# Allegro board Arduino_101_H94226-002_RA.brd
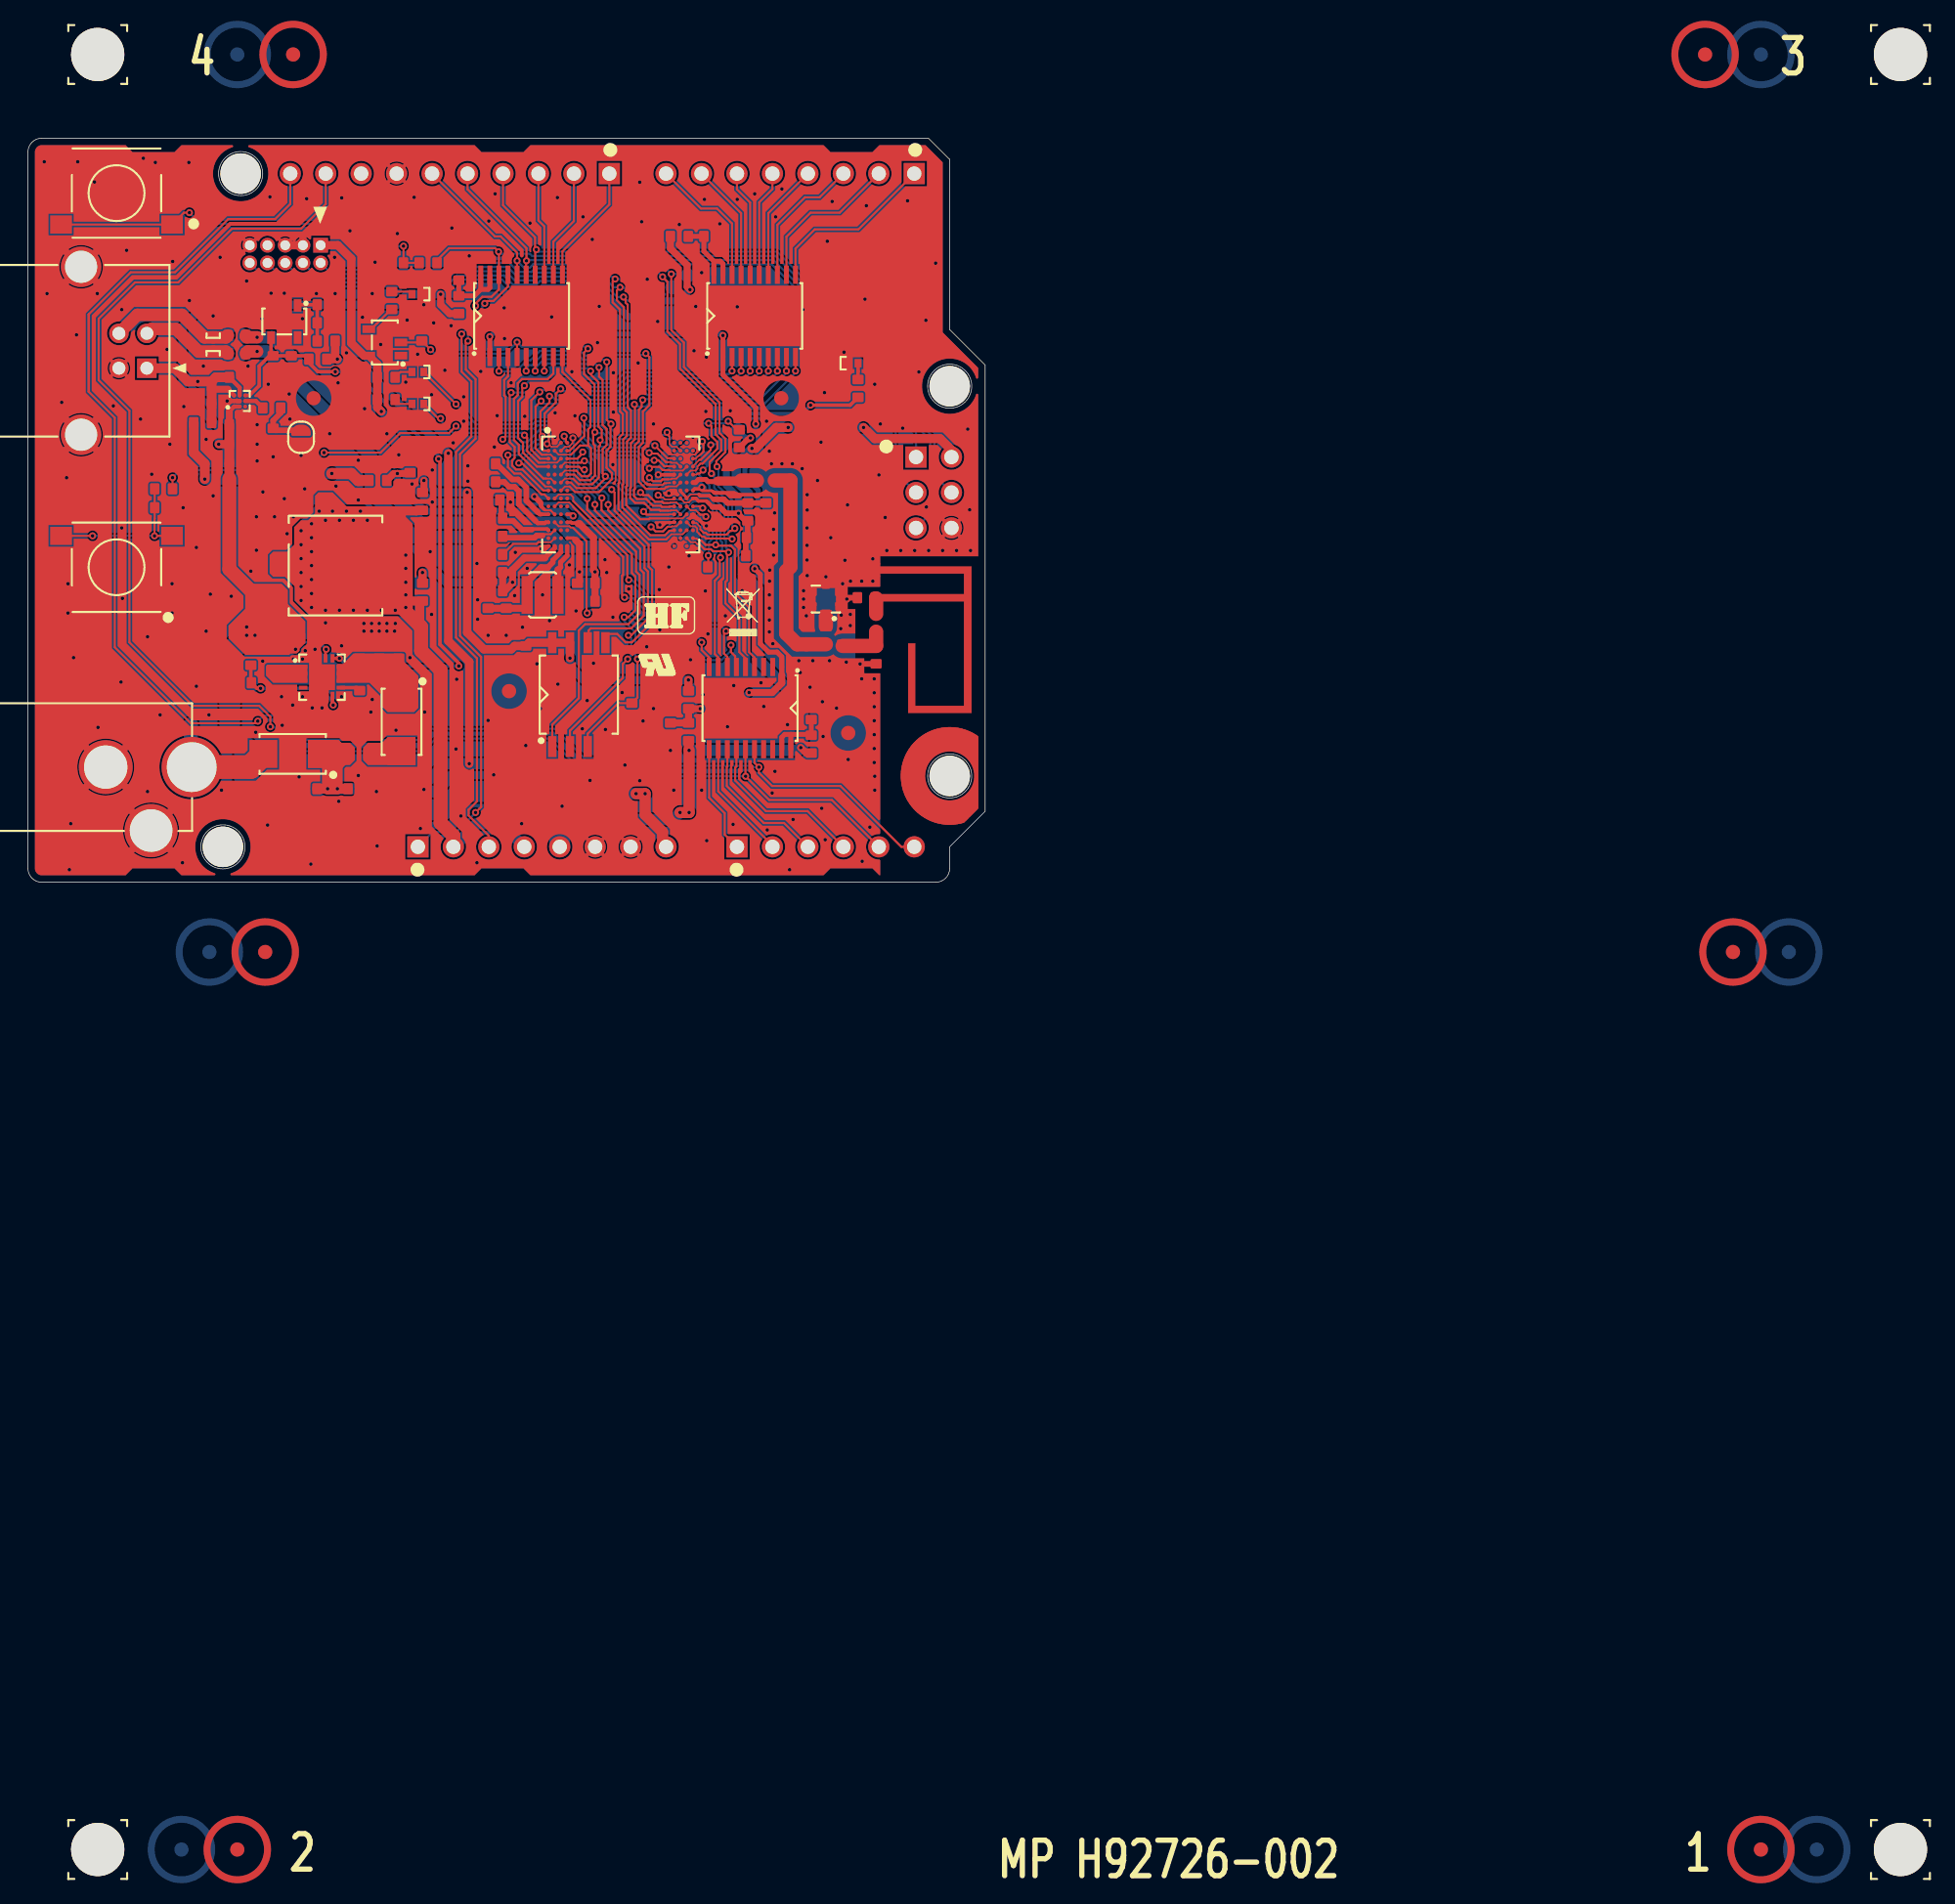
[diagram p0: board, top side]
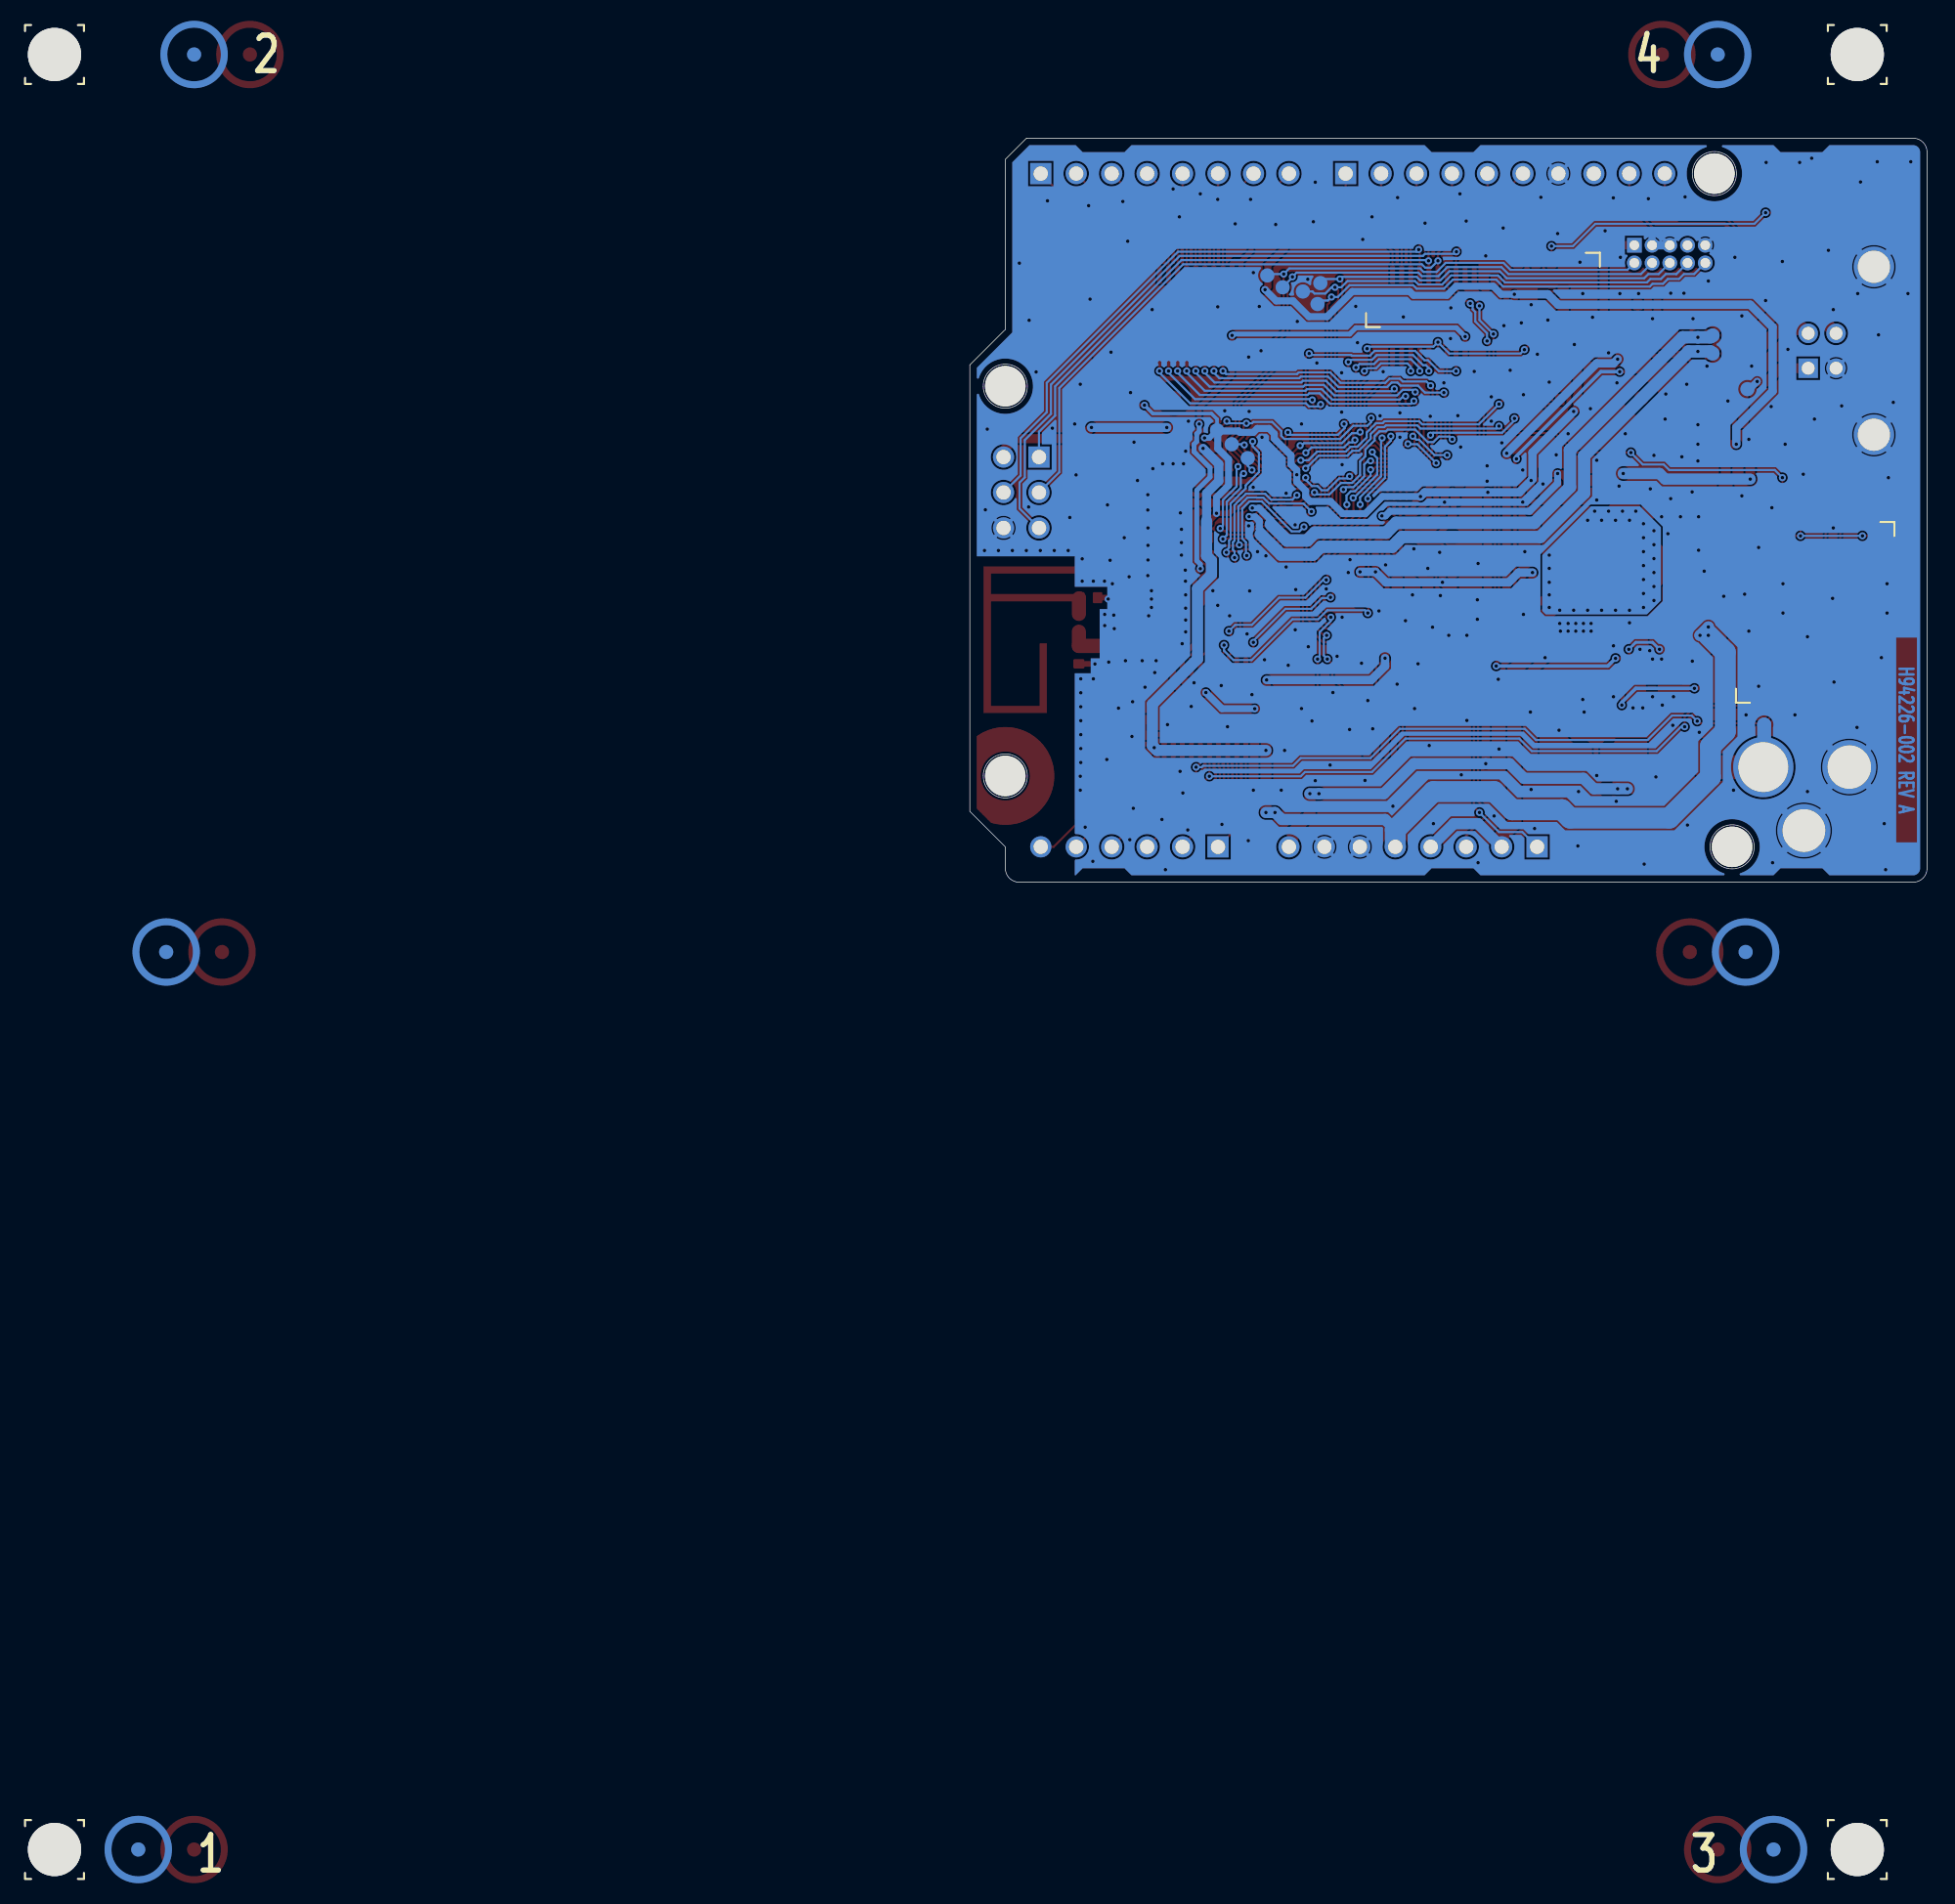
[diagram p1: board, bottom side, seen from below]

Outline 68.58 x 53.34 mm; copper layers: TOP, BOTTOM. Coordinates in mm from the lower left corner of the outline.

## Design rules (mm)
net group USBOTG_DPN: nets USBDN_CONN USBDP_CONN
net group 50OHM_L1>L2: nets BT_ANT_50 BT_AOUT_50 N385362 N385442
net group POWER_TRACE: nets CURIE_VBUS DC_IN_5V_20V N364156 N380754 PV_BATT USB_5P00_PWR V_1P8_ESR3 VDD_PLAT_1P8 VDD_PLAT_3P3 VSYS

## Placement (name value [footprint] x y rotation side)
C11  4.7uF  [0603X90H]  14.17 18 270 top
C12  4.7uF  [0603X90H]  25.17 16.7 180 top
C13  10UF  [0603X90H]  20.47 27.4 270 top
C14  22uF  [0603X90H]  20.17 17.5 90 top
C15  0.033uF  [0603X90H]  23.77 13.1 0 top
C16  4.7uF  [0603X90H]  23.77 16.7 180 top
C17  4.7uF  [0603X90H]  27.37 30 180 top
C18  4.7uF  [0603X90H]  15.07 36.2 90 top
C19  33pF  [0603X90H]  9.72 26.85 90 top
C20  10UF  [0603X90H]  52.87 26.55 0 top
C21  10UF  [0603X90H]  52.12 24.71 90 top
C22  0.1uF  [0603X90H]  52.07 23.41 90 top
C23  10UF  [0603X90H]  33.17 27.4 270 top
C24  0.1uF  [0603X90H]  33.37 26.1 270 top
C25  4.7uF  [0603X90H]  41.27 21.45 90 top
C26  0.1uF  [0603X90H]  41.27 20.15 90 top
C28  0.1uF  [0603X90H]  33.37 24.8 270 top
C29  4.7uF  [0603X90H]  32.97 19 0 top
C30  0.1uF  [0603X90H]  34.27 19 0 top
C31  4.7uF  [0603X90H]  33.37 20.9 270 top
C32  0.1uF  [0603X90H]  33.37 22.2 270 top
C33  4.7uF  [0603X90H]  39.37 20.8 0 top
C35  0.1uF  [0603X90H]  32.87 30 270 top
C36  0.1uF  [0603X90H]  20.07 6.7 270 top
C37  4.7nH  [0603X90H]  60.77 16.3 180 top
C38  NP  [0603X90H]  55.77 17.7 0 top
C39  0.1uF  [0603X90H]  15.07 32.8 90 top
C41  33pF  [0603X90H]  26.27 44.4 270 top
C42  4.7uF  [0603X90H]  12.52 34.3 270 top
C43  0.1uF  [0603X90H]  46.03 10.78 0 top
C44  0.1uF  [0603X90H]  35.67 16.3 0 top
C45  0.1uF  [0603X90H]  33.37 23.5 270 top
C46  NP  [0603X90H]  55.27 28.8 270 top
C47  NP  [0603X90H]  51.07 29.4 0 top
C48  0.1uF  [0603X90H]  32.87 28.7 270 top
C49  10UF  [0603X90H]  15.07 30 90 top
C50  4.7uF  [0603X90H]  23.57 6.7 90 top
C51  0.1uF  [0603X90H]  56.12 12.3 180 top
C52  0.1uF  [0603X90H]  30.87 43.8 180 top
C53  0.1uF  [0603X90H]  49.07 46.3 90 top
C54  0.1uF  [0603X90H]  21.37 41.4 90 top
C55  0.1uF  [0603X90H]  18.87 37.1 0 top
D10  GREEN  [LED_100X60X25H_SMLP13]  59.05 37.21 0 top
D13  GREEN  [LED_100X60X25H_SMLP13]  27.94 42.16 180 top
D14  GREEN  [LED_100X60X25H_SMLP13]  27.94 36.58 180 top
D15  SML-P11UTT86  [LED_100X60X25H_SMLP13]  27.94 34.29 180 top
D17  RSX501L-20TE25  [DIO2_450X260X220H]  18.97 9.2 180 top
D18  RSX501L-20TE25  [DIO2_450X260X220H]  26.77 11.5 270 top
ESD10  CLAMP  [DIO_SOD882]  13.27 37.4 270 top
ESD11  CLAMP  [DIO_SOD882]  13.27 39.7 90 top
J10  8 PIN SOCKET  [CONF1X8-254P_2104X240X850H_TH]  36.83 2.54 0 top
J11  10 PIN SOCKET  [CONF1X10-254P_2612X240X850H_TH]  30.23 50.8 180 top
J12  2X3 PIN HEADER  [CONM2X3-254P_762X500X860H_TH]  64.9 27.94 270 top
J13  8 PIN SOCKET  [CONF1X8-254P_2104X240X850H_TH]  54.61 50.8 180 top
J14  6 PIN SOCKET  [CONF1X6-254P_1596X240X850H_TH]  57.15 2.54 0 top
J15  20021111-00010T4LF  [CONM2X5-127P_1270X559X533H_TH]  18.43 45.03 180 top
J16  2DC-0005D200  [CON_JACK_880X1350X1135H_EJ508A]  5.59 8.26 270 top
J17  AU-Y1007-2-R USB  [CON_USB_1204X1650X1115_AUY1007]  3.81 38.1 90 top
J18  MHF4  [CONN_COAX_MHF4]  57.17 20.3 0 top
L10  2.2uH  [0806X100H]  17.87 16 90 top
L12  22uH  [COIL_300X300X120H_NRH3012]  36.87 20.6 0 top
L13  300Ohm_100M  [0603X90H]  23.72 9.2 90 top
NOREF  -  []  109.35 0 90 top
NOREF#2  -  []  80.16 -64.34 0 top
NOREF#3  -  []  0 1 0 top
NOREF#4  -  []  8.96 31.78 0 top
NOREF#5  -  [unnamed#2]  17 -5 0 top
NOREF#6  -  []  105.16 -64.34 0 top
NOREF#7  -  []  9 -9 0 top
NOREF#8  -  []  61.47 20.31 0 top
NOREF#9  -  []  62.45 9.7 0 top
NOREF#10  -  []  3.61 -74.34 90 top
NOREF#11  -  [unnamed#2]  20.47 34.7 0 top
NOREF#12  -  []  -70.12 -152.57 0 top
NOREF#13  -  []  105.16 54.34 180 top
NOREF#14  -  []  0 -71.34 0 top
NOREF#15  -  []  120.62 59.13 0 top
NOREF#16  -  []  59 -1 0 top
NOREF#17  -  []  1.36 0 90 top
NOREF#18  -  [unnamed#2]  58.77 10.7 0 top
NOREF#19  -  []  59 -9 180 top
NOREF#20  -  []  13.97 -60.8 0 top
NOREF#21  -  []  138.16 -8 90 top
NOREF#22  -  []  134.16 -69.34 0 top
NOREF#23  -  [unnamed#2]  34.47 13.7 0 top
NOREF#24  -  []  19.97 -70.8 0 top
NOREF#25  -  []  5 59.34 90 top
NOREF#26  -  []  130.16 54.34 180 top
NOREF#27  -  []  80.16 -9 0 top
NOREF#28  -  []  68.58 5.08 0 top
NOREF#29  -  []  5 59.34 0 top
NOREF#30  -  []  66.04 39.62 0 top
NOREF#31  -  []  26.91 53.34 90 top
NOREF#32  -  []  0.41 53.14 0 top
NOREF#33  -  []  44.87 20 0 top
NOREF#34  -  []  9 -1 0 top
NOREF#35  -  []  22 -71.34 0 top
NOREF#36  -  []  17 -5 0 top
NOREF#37  -  []  70.58 26.24 0 top
NOREF#38  -  []  59 -64.34 0 top
NOREF#39  -  []  1 0 0 top
NOREF#40  -  []  34 -1 0 top
NOREF#41  -  []  34 -9 180 top
NOREF#42  -  []  138.77 -2.21 0 top
NOREF#43  -  []  19 59.34 0 top
NOREF#44  -  []  68.58 5.08 0 top
NOREF#45  -  []  66.04 2.54 0 top
NOREF#46  -  []  15.24 50.8 0 top
NOREF#47  -  []  64.52 53.34 0 top
NOREF#48  -  []  124.16 -69.34 0 top
NOREF#49  -  []  66.04 0.17 0 top
NOREF#50  -  []  0 -22.73 0 top
NOREF#51  -  []  105.16 -1 0 top
NOREF#52  -  []  122.16 -5 0 top
NOREF#53  -  [unnamed#2]  124.16 -69.34 180 top
NOREF#54  -  []  34 54.34 180 top
NOREF#55  -  []  95.16 58.34 0 top
NOREF#56  -  []  -29.1 -119.83 0 top
NOREF#57  -  [unnamed#2]  15 -69.34 0 top
NOREF#58  -  []  5 -69.34 0 top
NOREF#59  -  []  105.16 -9 180 top
NOREF#60  -  []  13.97 2.54 0 top
NOREF#61  -  []  120.16 59.34 0 top
NOREF#62  -  []  0 61.34 0 top
NOREF#63  -  []  17 -5 0 top
NOREF#64  -  []  135.84 -70.48 0 top
NOREF#65  -  []  9 -9 180 top
NOREF#66  -  []  -10.69 95.32 0 top
NOREF#67  -  []  45.07 15.6 0 top
NOREF#68  -  []  34 -64.34 0 top
NOREF#69  -  [unnamed#2]  19 59.34 0 top
NOREF#70  -  []  104.97 -64.8 0 top
NOREF#71  -  [unnamed#2]  122.16 -5 180 top
NOREF#72  -  []  1 -63.34 0 top
NOREF#73  -  [unnamed#2]  5 59.34 0 top
NOREF#74  -  []  65.04 0 0 top
NOREF#75  -  []  13.97 2.54 0 top
NOREF#76  -  []  130.16 -9 0 top
NOREF#77  -  [unnamed#2]  134.16 59.34 180 top
NOREF#78  -  []  0 61.34 0 top
NOREF#79  -  []  130.16 -9 180 top
NOREF#80  -  []  136.16 -74.34 90 top
NOREF#81  -  [unnamed#2]  120.16 59.34 180 top
NOREF#82  -  []  105.16 -9 0 top
NOREF#83  -  []  51.17 19.8 0 top
NOREF#84  -  [unnamed#2]  53.97 34.7 0 top
NOREF#85  -  []  13.97 -60.8 0 top
NOREF#86  -  []  130.16 -1 0 top
NOREF#87  -  []  9 -9 0 top
NOREF#88  -  []  0 51.84 0 top
NOREF#89  -  []  231.19 -5.6 0 top
NOREF#90  -  []  -63.77 -150.03 0 top
NOREF#91  -  []  54.97 60.2 0 top
NOREF#92  -  []  15 -69.34 0 top
NOREF#93  -  []  123.92 -60.8 0 top
NOREF#94  -  []  66.04 7.62 0 top
NOREF#95  -  []  9 -64.34 0 top
NOREF#96  -  []  66.04 35.56 0 top
NOREF#97  -  []  66.04 51.82 0 top
NOREF#98  -  []  83.97 -69.8 0 top
NOREF#99  -  []  80.16 54.34 180 top
NOREF#100  -  []  138.08 63.65 0 top
NOREF#101  -  []  85.97 58.2 0 top
NOREF#102  -  []  218.79 72.88 0 top
NOREF#103  -  []  9 54.34 180 top
NOREF#104  -  []  174.48 43.2 0 top
NOREF#105  -  [unnamed#3]  0 0 0 top
NOREF#106  -  []  75.16 61.34 0 top
NOREF#107  -  []  80.16 -9 180 top
NOREF#108  -  []  42 -68.34 0 top
NOREF#109  -  []  59 54.34 180 top
NOREF#110  -  []  33.97 54.2 0 top
NOREF#111  -  []  130.16 -64.34 0 top
NOREF#112  -  []  68.58 37.08 0 top
NOREF#113  -  []  5 -69.34 0 top
NOREF#114  -  []  13.97 -60.8 0 top
NOREF#115  -  [unnamed#2]  134.16 -69.34 180 top
NOREF#116  -  []  80.16 -1 0 top
NOREF#117  -  []  15.24 50.8 0 top
NOREF#118  -  []  68.58 28.01 0 top
NOREF#119  -  [unnamed#2]  5 -69.34 0 top
NOREF#120  -  []  13.97 2.54 0 top
NOREF#121  -  [unnamed#2]  11 -69.34 180 bottom
NOREF#122  -  []  98.16 -68.34 180 bottom
NOREF#123  -  [unnamed#2]  13 -5 180 bottom
NOREF#124  -  []  41 58.34 180 bottom
NOREF#125  -  [unnamed#2]  124.16 59.34 0 bottom
NOREF#126  -  [unnamed#2]  128.16 -69.34 0 bottom
NOREF#127  -  [unnamed#2]  15 59.34 180 bottom
NOREF#128  -  [unnamed#2]  126.16 -5 0 bottom
R10  330  [0603X90H]  59.47 35.4 180 top
R12  22  [0603X90H]  12.52 32.95 270 top
R13  100  [0603X90H]  9.72 28.2 90 top
R14  1K  [0603X90H]  26.07 41.7 180 top
R15  330  [0603X90H]  25.67 36.2 90 top
R16  330  [0603X90H]  25.67 34.6 90 top
R18  0R  [0603X90H]  57.17 17.7 180 top
R19  0R  [0603X90H]  57.67 17 90 top
R23  100  [0603X90H]  28.67 44.4 90 top
R24  NP  [0603X90H]  48.07 22.6 90 top
R27  200K  [0603X90H]  56.12 9.9 180 top
R28  200K  [0603X90H]  30.87 41.4 180 top
R29  200K  [0603X90H]  46.67 46.3 90 top
R30  10K  [0603X90H]  50.97 31.8 180 top
R31  22  [0603X90H]  14.97 39.2 90 top
R32  22  [0603X90H]  14.97 37.9 90 top
R33  10K  [0603X90H]  47.33 10.78 180 top
R34  1.8K  [0603X90H]  47.33 13.08 0 top
R35  22  [0603X90H]  51.57 26.55 0 top
R57  10K  [0603X90H]  15.07 31.4 270 top
R58  0R  [0603X90H]  28.27 27.3 0 top
R59  0R  [0603X90H]  25.07 28.8 270 top
R62  10K  [0603X90H]  43.27 12.2 0 top
R63  0R  [0603X90H]  28.27 20.8 0 top
R65  200K  [0603X90H]  28.22 39.45 180 top
R70  10K  [0603X90H]  15.97 16.2 0 top
R71  10K  [0603X90H]  15.37 14.3 270 top
R73  402  [0603X90H]  17.57 31.9 180 top
R74  698  [0603X90H]  17.47 34 270 top
R75  1000  [0603X90H]  17.57 37.1 0 top
R77  10K  [0603X90H]  26.57 16.7 180 top
R81  3K 1%  [0603X90H]  20.77 37.5 270 top
R82  10K 1%  [0603X90H]  21.37 40.1 90 top
R83  1.5K 1%  [0603X90H]  21.37 38.8 270 top
RLC10  1.2pF  [0603X90H]  60.77 18.6 180 top
RLC11  NP  [0603X90H]  60.07 20.4 90 top
RLC12  10pF  [0603X90H]  52.87 28.8 90 top
SH10  Short_pad  [SHORT_140X180]  19.57 31.9 0 top
SW10  PTS645-S-M-43-SMTR92-LFS  [SW4_600X600X430H_SM_PTS645]  6.35 22.58 180 top
SW12  PTS645-S-M-43-SMTR92-LFS  [SW4_600X600X430H_SM_PTS645]  6.35 49.4 180 top
TPB10  T_POINT  [TP40]  48.67 30.4 180 bottom
TPB11  T_POINT  [TP40]  49.82 31.4 180 bottom
TPB12  T_POINT  [TP40]  47.27 43.5 180 bottom
TPB13  T_POINT  [TP40]  46.17 42.65 180 bottom
TPB14  T_POINT  [TP40]  43.47 42.95 180 bottom
TPB15  T_POINT  [TP40]  44.72 42.35 180 bottom
TPB16  T_POINT  [TP40]  43.67 41.45 180 bottom
TPB17  T_POINT  [TP40]  15.37 37.9 180 bottom
TPB18  T_POINT  [TP40]  15.37 39.2 180 bottom
TPB19  T_POINT  [TP40]  12.87 35.35 180 bottom
TPB20  T_POINT  [TP40]  11.67 11.3 180 bottom
TPB21  T_POINT  [TP40]  50.87 32.4 180 bottom
TPB22  T_POINT  [TP40]  45.87 38.1 180 bottom
TPB23  T_POINT  [TP40]  23.37 29.3 180 bottom
U10  TPS62153RGT  [QFN16-50P_300X300X100H_TR]  21.07 14.7 0 top
U11  LSF0108  [SOIC20-65P_440X650X120H]  52.07 40.6 90 top
U12  CURIE_V3  [BGA111_14X24-57P_805X1100X150H]  42.47 27.8 90 top
U13  FPF2496  [BGA9_3X3-40P_121X121X63H]  15.17 34.5 90 top
U14  LSF0108  [SOIC20-65P_440X650X120H]  35.37 40.6 90 top
U15  LSF0108  [SOIC20-65P_440X650X120H]  51.73 12.48 270 top
U16  SN74AUP1G34DBVR  [SOT23-5_160X290X145H]  25.57 38.7 180 top
U17  LM1117DTX-3.3 NOPB  [DPAK-3P_658X610X238H]  21.77 22.7 270 top
U201  W25Q16DVSSIG  [SOIC8-127P_528X528X216H]  39.47 13.45 90 top
U202  R3119N050A  [SOT23-5_160X290X120H]  18.37 40.2 270 top

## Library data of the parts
C11 C12 C15-C18 C22 C24-C26 C28-C33 C35 C42-C45 C48 C50-C53 = CAP NP
C13 C20 C23 C49 = CAP-NP_0: tolerance: 20%
C14 C19 C36 C39 C41 C54 C55 = CAP-NP_0
C21 = CAP NP: tolerance: 20%
C37 C38 C46 C47 = CAP NP_0
D10 D13-D15 = LED_6
D17 D18 = BAS40SL_1
ESD10 ESD11 = AOZ8131DI-05L_100312_000
J10 = 8 PIN SOCKET
J11 = 10 PIN SOCKET_2
J12 = jumper_0
J13 = 8 PIN SOCKET_0
J14 = 8 PIN SOCKET_3
J15 = SHF-105-01-L-D-TH_0
J16 = EJ508A_0
J17 = USB TYPE B_2
J18 = COAX-CONN_2
L10 L13 = INDCT,PWR,63X79,1.9A,2.2uH
L12 = INDCT,PWR,22uH
R10 R12-R16 R23 R27-R29 R31 R32 R35 R65 = RESISTOR
R18 R19 R58 R63 = RESD,0402,5%,1/16W,0: tolerance: 5%
R24 = R_5
R30 R33 R34 R57 R62 R70 R71 R77 R81-R83 = R_5: tolerance: <TOL>
R59 = RESISTOR: tolerance: 5%
R73-R75 = R_5: tolerance: 1%
RLC10-RLC12 = RLC
SH10 = Shorting_pad_2
SW10 SW12 = TCFC2QR1_1
TPB10-TPB23 = T_POINT_S_3
U10 = TPS62143RGT_5
U11 U14 U15 = LSF0108
U12 = CURIE_23
U13 = FPF2496
U16 = SN74AUP1G07DBVR
U17 = NCP1117DT33T5G_0
U201 = M25P16_1
U202 = R3120NxxxA_0

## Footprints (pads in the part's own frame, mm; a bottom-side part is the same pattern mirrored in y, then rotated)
0603X90H
  custom 0.17x0.17 smd: 1(0,0.64) 2(0,-0.64)
0806X100H
  custom 0.2x0.2 smd: 1(-0.8,0) 2(0.8,0)
BGA9_3X3-40P_121X121X63H
  round 0.28 smd: A1(-0.4,0.4) A2(0,0.4) A3(0.4,0.4) B1(-0.4,0) B2(0,0) B3(0.4,0) C1(-0.4,-0.4) C2(0,-0.4) C3(0.4,-0.4)
BGA111_14X24-57P_805X1100X150H
  round 0.28 smd: A2(3.705,4.73) A3(3.705,4.28) A4(3.705,3.83) A21(3.705,-3.83) A22(3.705,-4.28) A23(3.705,-4.73) A24(3.705,-5.18) B1(3.135,5.18) B2(3.135,4.73) B3(3.135,4.28) B4(3.135,3.83) B21(3.135,-3.83) B22(3.135,-4.28) B23(3.135,-4.73) B24(3.135,-5.18) C1(2.565,5.18) C2(2.565,4.73) C3(2.565,4.28) C4(2.565,3.83) C21(2.565,-3.83) C22(2.565,-4.28) C23(2.565,-4.73) C24(2.565,-5.18) D1(1.995,5.18) D2(1.995,4.73) D3(1.995,4.28) D4(1.995,3.83) D21(1.995,-3.83) D22(1.995,-4.28) D23(1.995,-4.73) D24(1.995,-5.18) E1(1.425,5.18) E2(1.425,4.73) E3(1.425,4.28) E4(1.425,3.83) E21(1.425,-3.83) E22(1.425,-4.28) E23(1.425,-4.73) E24(1.425,-5.18) F1(0.855,5.18) F2(0.855,4.73) F3(0.855,4.28) F4(0.855,3.83) F21(0.855,-3.83) F22(0.855,-4.28) F23(0.855,-4.73) F24(0.855,-5.18) G1(0.285,5.18) G2(0.285,4.73) G3(0.285,4.28) G4(0.285,3.83) G21(0.285,-3.83) G22(0.285,-4.28) G23(0.285,-4.73) G24(0.285,-5.18) H1(-0.285,5.18) H2(-0.285,4.73) H3(-0.285,4.28) H4(-0.285,3.83) H21(-0.285,-3.83) H22(-0.285,-4.28) H23(-0.285,-4.73) H24(-0.285,-5.18) J2(-0.855,4.73) J3(-0.855,4.28) J4(-0.855,3.83) J21(-0.855,-3.83) J22(-0.855,-4.28) J23(-0.855,-4.73) J24(-0.855,-5.18) K2(-1.425,4.73) K3(-1.425,4.28) K4(-1.425,3.83) K21(-1.425,-3.83) K22(-1.425,-4.28) K23(-1.425,-4.73) K24(-1.425,-5.18) L1(-1.995,5.18) L2(-1.995,4.73) L3(-1.995,4.28) L4(-1.995,3.83) L21(-1.995,-3.83) L22(-1.995,-4.28) L23(-1.995,-4.73) L24(-1.995,-5.18) M2(-2.565,4.73) M3(-2.565,4.28) M4(-2.565,3.83) M21(-2.565,-3.83) M22(-2.565,-4.28) M23(-2.565,-4.73) M24(-2.565,-5.18) N2(-3.135,4.73) N3(-3.135,4.28) N4(-3.135,3.83) N21(-3.135,-3.83) N22(-3.135,-4.28) N23(-3.135,-4.73) N24(-3.135,-5.18) P1(-3.705,5.18) P2(-3.705,4.73) P3(-3.705,4.28) P4(-3.705,3.83) P21(-3.705,-3.83) P22(-3.705,-4.28) P23(-3.705,-4.73) P24(-3.705,-5.18)
  round 0.27 smd: J1(-0.855,5.18) K1(-1.425,5.18) M1(-2.565,5.18) N1(-3.135,5.18)
COIL_300X300X120H_NRH3012
  rect 0.8x2.7 smd: 1(-1.1,0) 2(1.1,0)
CON_JACK_880X1350X1135H_EJ508A
  round 4.32 hole 3.56: 1(0,6.15)
  round 3.81 hole 3.05: 2(4.55,3.24)
  round 3.86 hole 3.1: 3(0,-0.01)
CON_USB_1204X1650X1115_AUY1007
  rect 1.4x1.4 hole 0.92: 1(-1.25,-4.71)
  round 1.4 hole 0.92: 2(1.25,-4.71) 3(1.25,-2.71) 4(-1.25,-2.71)
  round 2.9 hole 2.3: 5(-6.02,0) 6(6.02,0)
CONF1X6-254P_1596X240X850H_TH
  rect 1.52x1.52 hole 1.02: 1(-6.35,0)
  round 1.52 hole 1.02: 2(-3.81,0) 3(-1.27,0) 4(1.27,0) 5(3.81,0) 6(6.35,0)
CONF1X8-254P_2104X240X850H_TH
  rect 1.52x1.52 hole 1.02: 1(-8.89,0)
  round 1.52 hole 1.02: 2(-6.35,0) 3(-3.81,0) 4(-1.27,0) 5(1.27,0) 6(3.81,0) 7(6.35,0) 8(8.89,0)
CONF1X10-254P_2612X240X850H_TH
  rect 1.52x1.52 hole 1.02: 1(-11.43,0)
  round 1.52 hole 1.02: 2(-8.89,0) 3(-6.35,0) 4(-3.81,0) 5(-1.27,0) 6(1.27,0) 7(3.81,0) 8(6.35,0) 9(8.89,0) 10(11.43,0)
CONM2X3-254P_762X500X860H_TH
  rect 1.52x1.52 hole 1.02: 1(-2.54,-1.27)
  round 1.52 hole 1.02: 2(-2.54,1.27) 3(0,-1.27) 4(0,1.27) 5(2.54,-1.27) 6(2.54,1.27)
CONM2X5-127P_1270X559X533H_TH
  rect 1.06x1.06 hole 0.7: 1(-2.54,-0.635)
  round 1.06 hole 0.7: 2(-2.54,0.635) 3(-1.27,-0.635) 4(-1.27,0.635) 5(0,-0.635) 6(0,0.635) 7(1.27,-0.635) 8(1.27,0.635) 9(2.54,-0.635) 10(2.54,0.635)
CONN_COAX_MHF4
  rect 0.6x0.5 smd: 1(0,-1)
  custom 0.145x0.145 smd: 2(-0.96,0) 4(0.96,0)
  rect 0.5x0.5 smd: 3(0,1)
DIO2_450X260X220H
  rect 2x2 smd: A(2.1,0) K(-2.1,0)
DIO_SOD882
  rect 0.3x0.55 smd: 1(-0.35,0) 2(0.35,0)
DPAK-3P_658X610X238H
  rect 1.6x2.5 smd: 1(-2.285,-4.83) 3(2.285,-4.83)
  rect 5.8x6 smd: 2(0,2)
LED_100X60X25H_SMLP13
  rect 0.5x0.6 smd: A(0.425,0) K(-0.425,0)
QFN16-50P_300X300X100H_TR
  rect 0.6x0.27 smd: 1(-1.35,0.75) 2(-1.35,0.25) 3(-1.35,-0.25) 4(-1.35,-0.75) 9(1.35,-0.75) 10(1.35,-0.25) 11(1.35,0.25) 12(1.35,0.75)
  rect 0.27x0.6 smd: 5(-0.75,-1.35) 6(-0.25,-1.35) 7(0.25,-1.35) 8(0.75,-1.35) 13(0.75,1.35) 14(0.25,1.35) 15(-0.25,1.35) 16(-0.75,1.35)
  rect 1.7x1.7 smd: 17(0,0)
SHORT_140X180
  custom 0.2x0.2 smd: 1(0,0.5) 2(0,-0.5)
SOIC8-127P_528X528X216H
  rect 1.5x0.6 smd: 1(-3.725,1.905) 2(-3.725,0.635) 3(-3.725,-0.635) 4(-3.725,-1.905) 5(3.725,-1.905) 6(3.725,-0.635) 7(3.725,0.635) 8(3.725,1.905)
SOIC20-65P_440X650X120H
  rect 1.3x0.35 smd: 1(-2.95,2.925) 2(-2.95,2.275) 3(-2.95,1.625) 4(-2.95,0.975) 5(-2.95,0.325) 6(-2.95,-0.325) 7(-2.95,-0.975) 8(-2.95,-1.625) 9(-2.95,-2.275) 10(-2.95,-2.925) 11(2.95,-2.925) 12(2.95,-2.275) 13(2.95,-1.625) 14(2.95,-0.975) 15(2.95,-0.325) 16(2.95,0.325) 17(2.95,0.975) 18(2.95,1.625) 19(2.95,2.275) 20(2.95,2.925)
SOT23-5_160X290X120H
  rect 0.9x0.55 smd: 1(-1.15,0.95) 2(-1.15,0) 3(-1.15,-0.95) 4(1.15,-0.95) 5(1.15,0.95)
SOT23-5_160X290X145H
  rect 0.9x0.55 smd: 1(-1.15,0.95) 2(-1.15,0) 3(-1.15,-0.95) 4(1.15,-0.95) 5(1.15,0.95)
SW4_600X600X430H_SM_PTS645
  rect 1.55x1.3 smd: 1(-3.975,2.25) 2(3.975,2.25) 3(-3.975,-2.25) 4(3.975,-2.25)
TP40
  round 1.016 smd: 1(0,0)
unnamed#2
  round 1.016 smd: (0,0)
unnamed#3
  round 2.9 hole 3.2 unplated: (13.97,2.54) (15.24,50.8) (66.04,35.56) (66.04,7.62)

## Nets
GND: C11.2 C12.2 C13.2 C14.2 C15.2 C16.2 C17.2 C18.2 C19.2 C20.2 C21.2 C22.2 C23.2 C24.2 C25.2 C26.2 C28.2 C29.2 C30.2 C31.2 C32.2 C33.2 C35.2 C36.2 C37.1 C38.1 C39.2 C41.2 C42.2 C43.2 C44.2 C45.2 C46.1 C47.1 C48.2 C49.2 C50.2 C51.2 C52.2 C53.2 C54.2 C55.2 D10.K D13.K ESD10.2 ESD11.2 J10.6(GND1) J10.7(GND2) J11.7(GND) J12.6(GND) J15.3(GND1) J15.5(GND2) J15.9(GND3) J16.2(GND1) J16.3(GND2) J17.4(GND) J17.5(S1) J17.6(S2) J18.2(GND1) J18.3(GND2) J18.4(GND3) R24.1 R57.1 R62.2 R65.2 R71.2 R73.1 R75.2 R77.2 R82.2 RLC11.1 SH10.2(P2) SW10.1 SW10.2 SW12.3 SW12.4 TPB22.1(TP) TPB23.1(TP) U10.5(FB) U10.6(AGND) U10.7(FSW) U10.15(PGND1) U10.16(PGND2) U10.17(THERM) U11.1(GND) U12.A2(GND2) U12.A24(GND7) U12.C23(GND4) U12.G21(GND6) U12.G24(GND5) U12.K24(VIN_1) U12.L21(AGND) U12.N21(VIN_2) U12.P1(GND1) U12.P22(GND3) U12.P24(GND8) U13.A2(GND1) U13.B2(GND2) U14.1(GND) U15.1(GND) U16.3(GND) U17.1(GND) U201.4(VSS) U202.2(GND1) U202.3(GND2)
VDD_PLAT_1P8: C28.1 U12.M2(VDD_PLAT_1P8)
VDD_PLAT_3P3: C21.1 C22.1 C44.1 J15.1(VCC) R10.1 R15.1 R16.1 R30.1 R34.1 R35.2 R58.1 TPB21.1(TP) U12.E21(AON_IO_VCC) U12.H22(CMP_3P3_VCC) U12.H24(VDD_BLE_SEN) U12.K2(BUCK_VSEL) U16.5(VCC) U201.7(H\O\L\D\) U201.8(VCC)
AD0: J14.1(AD0) U15.11(B8)
AD1: J14.2(AD1) U15.12(B7)
AD2: J14.3(AD2) U15.13(B6)
AD3: J14.4(AD3) U15.14(B5)
AD4_SDA: J11.9(AD4/SDA) J14.5(AD4/SDA) U15.15(B4)
AD5_SCL: J11.10(AD5/SCL) J14.6(AD5/SCL) U15.16(B3)
AD09/SS1_3V_AD5: U12.K21(UART1_RTS/AN09) U12.N24(I2C0_SS_SCL) U15.5(A3)
AD10/SS2_3V_AD0: U12.J2(GPIO/AIN_10) U15.10(A8)
AD11/SS3_3V_AD1: U12.H21(GPIO/AIN_11) U15.9(A7)
AD12/SS4_3V_AD2: U12.H2(GPIO/AIN_12) U15.8(A6)
AD13/SS5_3V_AD3: U12.L2(GPIO/AIN_13) U15.7(A5)
AD14/SS6_3V_AD4: U12.C24(GPIO/AIN_14) U12.N23(I2C0_SS_SDA) U15.6(A4)
AREF: J11.8(AREF)
ATPCTS/IO9_3V_IO14: U12.J22(UART1_CTS) U14.4(A2)
ATPMISO/IO1_3V_IO12: U12.B22(SPI1_M_MISO) U12.G3(ATP_SPI_S_MISO) U14.6(A4)
ATPMOSI/IO3_3V_IO11: U12.E22(SPI1_M_MOSI) U12.F4(ATP_SPI_S_MOSI) U14.7(A5)
ATPSCK/IO2_3V_IO13: R65.1 U12.C21(SPI1_M_SCK) U12.E4(ATP_SPI_S_SCK) U14.5(A3) U16.2(A)
ATPSS/IO0_3V_IO10: U12.D22(SPI1_M_CS0) U12.F3(ATP_SPI_S_CS) U14.8(A6)
BT_ANT_50: C38.2 C46.2 R18.1 R19.1 RLC12.2
BT_AOUT_50: C47.2 RLC12.1 U12.F24(BLE_RF)
CURIE_VBUS: R12.2 R59.2
DBG_AP_JTAG_TCK: J15.4(TCLK) TPB13.1(TP) U12.L23(ATP_TCK)
DBG_AP_JTAG_TDI: J15.8(TDI) TPB15.1(TP) U12.M21(ATP_TDI)
DBG_AP_JTAG_TDO: J15.6(TDO) TPB14.1(TP) U12.M23(ATP_TDO)
DBG_AP_JTAG_TMS: J15.2(TMS) TPB12.1(TP) U12.L24(ATP_TMS)
DBG_AP_JTAG_TRST_N: J15.10(RESET) TPB16.1(TP) U12.K23(ATP_TRST_B)
DC_IN_5V_20V: C36.1 C50.1 D17.K J10.8(VIN) L13.1 R81.1 R83.1
DC_IN_5V_20V_FIL: D18.A L13.2
DC_IN_JACK: D17.A J16.1(DC+) TPB20.1(TP)
I2S_TSCK/IO18_3V_IO2: U11.8(A6) U12.C2(I2S_TSCK)
I2S_TWS/IO19_3V_IO4: U11.6(A4) U12.C1(I2S_TWS)
I2S_TXD/IO20_3V_IO7: U11.3(A1) U12.D1(I2S_TXD)
IO0/RXD: J13.1(IO0/RXD) U11.11(B8)
IO1/TXD: J13.2(IO1/TXD) U11.12(B7)
IO2: J13.3(IO2) U11.13(B6)
IO3/PWM0: J13.4(IO3/PWM) U11.14(B5)
IO4: J13.5(IO4) U11.15(B4)
IO5/PWM1: J13.6(IO5/PWM) U11.16(B3)
IO6/PWM2: J13.7(IO6/PWM) U11.17(B2)
IO7: J13.8(IO7) U11.18(B1)
IO8: J11.1(IO8) U14.11(B8)
IO9/PWM3: J11.2(IO9/PWM) U14.12(B7)
IO10/SS: J11.3(SS/PWM) U14.13(B6)
IO11/MOSI: J11.4(MOSI/PWM) J12.4(MOSI) U14.14(B5)
IO12/MISO: J11.5(MISO) J12.1(MISO) U14.15(B4)
IO13/SCK: J11.6(SCK) J12.3(SCK) U14.16(B3)
IO14_NEW: J10.1(N/A) U14.17(B2)
M_RESET: R13.2 U12.D23(MRESET_B)
MISO1/IO9_3V_IO8: U12.B2(I2S_RSCK) U12.E3(PLT_CLK_0) U14.10(A8)
NOR_SWD_SCL: TPB11.1(TP) U12.D24(BLE_SW_CLK)
NOR_SWD_SDA: TPB10.1(TP) U12.E24(BLE_SWDIO)
PV_BATT: C23.1 C24.1 U12.M1(PV_BATT)
PWM0/SS10_3V_IO3: U11.7(A5) U12.B1(I2S_RWS) U12.H1(PWM0_OUT)
PWM1/SS11_3V_IO5: U11.5(A3) U12.A3(I2S_RXD) U12.G2(PWM1_OUT)
PWM2/SS12_3V_IO6: U11.4(A2) U12.G1(PWM2_OUT)
PWM3/SS13_3V_IO9: U12.F2(PWM3_OUT) U14.9(A7)
RST_SKETCH: J10.3(RESET) J12.5(R\E\S\E\T\) R23.2 U14.18(B1)
RST_SKETCH_3V: U12.F22(ATP_INT0) U14.3(A1)
RXD1/SS9_3V_IO0: U11.10(A8) U12.K22(UART1_RX)
RXLED: D15.K U12.C3(SPI0_M_CS2)
SP0_CLK_MEM: U12.C4(SPI0_M_SCK) U201.6(SCK)
SP0_CS0_MEM: U12.B3(SPI0_M_CS0) U201.1(C\S\)
SP0_MISO_MEM: U12.D4(SPI0_M_MISO) U201.2(MISO)
SP0_MOSI_MEM: U12.D3(SPI0_M_MOSI) U201.5(MOSI)
SP0_WP_MEM~: R62.1 U12.A4(SPI0_M_CS1) U201.3(W\P\)
TRIG_TRUE_D: C55.1 R75.1 R81.2 U10.13(ENA) U13.C3(ONB) U202.4(DOUT)
TXD1/SS8_3V_IO1: U11.9(A7) U12.J21(UART1_TX)
TXLED: D14.K U12.D21(SPI1_M_CS1)
USB_5P00_PWR: C18.1 C42.1 J17.1(VBUS) R12.1 TPB19.1(TP) U13.A3(VIN1) U13.B3(VIN2)
USBDN_CONN: R32.2 TPB17.1(TP) U12.J23(USB_DM)
USBDP_CONN: R31.2 TPB18.1(TP) U12.J24(USB_DP)
V_1P8_ESR3: C29.1 C30.1 L12.1 U12.P3(VDD_HOST_1P8)
V_3P3SRC_VDD1: C13.1 J10.2(IOREF) J10.4(3V3) R58.2 R63.2 U17.2(OUT)
V_3P5_VREFA: C43.1 R33.2 R34.2 U11.2(VREF_A) U14.2(VREF_A) U15.2(VREF_A)
V_5P00SRC_VDD1: C11.1 C14.1 C39.1 C49.1 J10.5(5V0) J12.2(5V0) L10.2 R27.1 R28.1 R29.1 R33.1 R57.2 R70.1 U10.14(VOS) U13.A1(VOUT1) U13.B1(VOUT2) U17.3(IN)
VSYS: C25.1 C26.1 C31.1 C32.1 C33.1 R63.1 U12.L4(VSYS) U12.N4(ESR2_VBATT) U12.P2(ESR1_VBATT)
N137369: ESD11.1 J17.3(DAT+) R31.1
N350266: R30.2 U12.B4(ATP_RST_B) U12.E23(POR_B)
N352539: R24.2 U12.L22(BATT_ISET)
N364156: L12.2 U12.P4(ESR3_LX)
N380754: C35.1 U12.K1(BUCK_VOUT)
N385362: J18.1(ANT-IN) R18.2
N385382: RLC10.2 RLC11.2
N385442: C37.2 R19.2 RLC10.1
N441562: ESD10.1 J17.2(DAT-) R32.1
N463771: C45.1 U12.N2(VDD_PLAT_3P3)
N498391: C20.1 R35.1 U12.G22(COMP_AREF) U12.H23(ADC_3P3_VCC)
N521217: C17.1 R59.1 U12.K4(VDD_USB)
N544606: C12.1 C16.1 D18.K R77.1 U10.10(AVIN) U10.11(PVIN1) U10.12(PVIN2)
N545273: L10.1 U10.1(SW1) U10.2(SW2) U10.3(SW3)
N616057: C48.1 U12.L1(LDO1P8_VOUT)
N656910: C51.1 R27.2 U15.19(VREF_B) U15.20(EN)
N656990: C53.1 R29.2 U11.19(VREF_B) U11.20(EN)
N657094: C52.1 R28.2 U14.19(VREF_B) U14.20(EN)
N692018: R73.2 R74.1 SH10.1(P1)
N692192: R74.2 U13.C2(ISET)
N704436: C15.1 U10.9(SS/TR)
N704444: R70.2 R71.1 U10.8(DEF)
N724575: C41.1 R23.1 SW12.1 SW12.2
N724587: C19.1 R13.1 SW10.3 SW10.4
N726409: D10.A R10.2
N726427: D14.A R15.2
N726455: D15.A R16.2
N765836: C54.1 R82.1 R83.2 U202.1(VDD)
N7255913: R14.1 U16.4(Y)
N7256071: D13.A R14.2

Pads without a net: J15 7; U10 4; U12 A21 A22 A23 B21 B23 B24 C22 D2 E1 E2 F1 F21 F23 G4 G23 H3 H4 J1 J3 J4 K3 L3 M3 M4 M22 M24 N1 N3 N22 P21 P23; U13 C1; U15 3 4 17 18; U16 1; U202 5

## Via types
v1: diameter 0.508, hole 0.254, TOP to BOTTOM, 564 vias

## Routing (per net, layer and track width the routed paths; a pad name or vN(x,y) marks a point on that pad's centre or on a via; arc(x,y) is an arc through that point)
GND: length 209.8
  TOP w0.116: 48.06,30.93 47.78,30.65 47.48,30.65 U12.C23
  TOP w0.15: 48.06,30.93 48.06,31.11 47.66,31.51
  TOP w0.2: U12.L21 46.02,25.81 46,25.78 45.44,25.78 v1(45.28,25.62)
  TOP w0.22: U12.K24 47.67,26.38 48.05,26 48.07,26 48.49,25.58 48.56,25.58 48.59,25.55 v1(48.61,25.55)
  TOP w0.25: 20.82,14.45 U10.17 ; 20.82,14.45 20.32,13.95 U10.5 20.32,12.55 v1(20.37,12.5) ; 20.82,14.45 U10.6 20.82,12.75 v1(21.07,12.5) 21.32,12.75 U10.7 21.32,14.45 U10.17 ; U10.17 20.82,14.95 ; J15.9 16.41,46.18 ; J15.9 15.38,45.15 ; J15.9 15.38,46.18 ; U10.16 20.32,15.45 20.82,14.95 ; J17.4 7.15,37.48 ; J17.4 5.89,37.48 ; J17.4 7.15,36.22 ; J17.4 5.89,36.22 ; v1(47.97,23.7) 47.97,23.78 U12.P24 ; v1(37.77,31.9) 37.74,31.87 U12.A2 ; 42.5,1.86 J10.7 ; J10.7 43.86,3.22 ; J10.7 43.86,1.86 ; J10.7 42.5,3.22 ; 20.82,14.95 U10.15 ; 25.74,51.48 J11.7 ; J11.7 27.09,51.48 ; J11.7 25.74,50.12 ; J11.7 27.09,50.12 ; 65.49,24.72 J12.6 ; J12.6 66.84,24.72 ; J12.6 65.49,26.08 ; J12.6 66.84,26.08 ; U12.P1 37.09,23.9 v1(36.77,23.9) ; U12.G21 46.07,28.09 45.92,27.93 v1(45.92,27.88) ; U12.N21 45.92,24.28 v1(45.92,22.6) ; J10.6 41.32,3.22 ; J10.6 39.96,3.22 ; J10.6 41.32,1.86 ; J10.6 39.96,1.86 ; U12.G24 47.77,28.2 48.17,28.2 v1(48.28,28.31) ; 17.92,46.18 J15.5 18.95,46.18
  TOP w0.3: U13.B2 U13.A2 v1(14.27,34.5) ; v1(12.57,37) 12.77,37 12.82,37.05 ESD10.2 ; v1(47.65,31.9) U12.A24 47.66,31.51 ; ESD11.2 v1(13.27,40.6) ; v1(47.37,23.4) 47.22,23.4 46.75,23.87 U12.P22
  TOP w0.35: 32.45,37.65 v1(32.45,36.62) ; v1(55.33,15.03) 54.71,15.03 54.66,15.08 U15.1 ; U11.1 v1(48.61,37.65)
  TOP w0.4: v1(16.37,26.2) 16.37,25.56 U17.1 ; C15.2 24.31,12.46 v1(24.57,12.2) ; R65.2 28.23,40.1 v1(29.07,40.1) ; v1(56.57,28.8) C46.1 ; v1(59.62,15.65) 60.77,15.65 C37.1 ; v1(11.17,34.1) 11.37,34.3 C42.2 ; C20.2 52.87,25.9 53.42,25.35 v1(53.42,25.3) ; U17.1 16.37,24.42 v1(16.37,23.8) ; U17.1 17.67,25.72 v1(17.67,26.2) ; U17.1 v1(18.57,24.98) ; v1(34.27,17.7) C30.2 ; 10.33,5.21 10.31,5.19 ; C47.1 52.06,30.04 52.92,30.9 v1(53.12,30.9) ; v1(16.42,30.2) 15.91,30.2 C49.2 ; 7.32,2.2 7.34,2.22 ; v1(32.22,20.25) 32.22,20.39 C31.2 ; v1(10.33,19.3) v1(10.33,21.4) ; C26.2 v1(41.91,19) ; v1(55.57,19.7) 55.97,19.7 56.21,19.94 J18.2 ; C25.2 41.91,21.64 41.47,22.08 v1(41.47,22.2) ; RLC11.1 58.67,20.4 v1(58.67,20.3) J18.4 ; v1(55.57,20.9) 56.21,20.9 J18.2 ; v1(47.37,23.4) 47.43,23.34 R24.1 ; v1(32.97,17.7) C29.2 ; v1(3.57,51.65) SW12.4 v1(1.17,51.65) ; SW12.3 10.33,51.6 ; 10.33,51.6 v1(9.13,51.6) ; 10.33,51.6 v1(11.53,51.6) ; v1(31.62,44.9) 31.16,44.44 C52.2 ; C51.2 v1(56.92,12.94) ; C33.2 39.27,20.06 v1(39.27,19.45) ; v1(2.87,21.4) 2.87,20.83 SW10.2 2.87,19.84 v1(2.87,19.3) ; v1(16.42,31.4) R57.1 ; D10.K 58.62,37.84 v1(58.47,38) ; v1(49.57,47.2) 49.71,47.06 C53.2 ; v1(32.17,22.85) 32.17,22.76 C32.2 ; C21.2 52.76,24.66 53.07,24.35 v1(53.42,24.35) ; J18.2 v1(55.57,20.3) ; v1(24.87,44.45) 25.58,44.45 C41.2 ; C22.2 52.75,23.45 v1(53.42,23.45) ; v1(31.52,29.85) 32.08,29.85 C35.2 ; v1(58.37,21.4) 58.13,21.16 J18.4 ; v1(27.17,40.3) 27.17,40.1 U16.3 ; 7.32,5.21 7.34,5.19 ; J18.4 58.13,19.92 58.27,19.78 v1(58.27,19.15) ; C18.2 15.77,36.26 v1(15.77,37) ; C13.2 v1(19.83,28.2) ; v1(28.37,41.4) D13.K ; C11.2 v1(12.77,18) ; C19.2 v1(11.12,26.85) ; v1(16.42,32.8) C39.2 ; U202.2 v1(18.37,42.23) ; U202.3 v1(17.42,42.23) ; 10.33,2.2 10.31,2.22
  TOP w0.5: J18.3 v1(57.17,21.9) ; U201.4 v1(41.38,10.95) ; 19.7,45.67 19.7,46.37 ; 7.34,5.19 8.83,3.7 ; 8.83,3.7 10.31,2.22 ; 8.83,3.7 7.34,2.22 ; 8.83,3.7 10.31,5.19 ; C48.2 32.23,27.7 C23.2 32.73,27.2 C24.2 C28.2 C45.2 C32.2 C31.2 ; C48.2 32.18,28.75 v1(31.52,28.75) ; C48.2 C35.2 ; v1(24.97,6.5) 24.77,6.7 C50.2 ; J17.6 4.97,45.28 ; J17.6 2.65,42.96 ; J17.6 2.65,45.28 ; J17.6 4.97,42.96 ; J17.5 4.97,30.92 ; J17.5 2.65,33.24 ; J17.5 2.65,30.92 ; J17.5 4.97,33.24 ; v1(22.01,42.2) C54.2 R82.2 ; C44.2 v1(36.47,15.66) ; SH10.2 v1(19.57,30.6) ; J16.3 7.08,9.76 ; J16.3 4.07,6.75 ; J16.3 7.08,6.75 ; J16.3 4.07,9.76 ; v1(26.57,30.64) C17.2 ; v1(55.77,19.1) C38.1 ; R73.1 v1(17.57,30.5) ; C43.2 v1(46.03,9.45) ; R62.2 v1(44.07,11.56) ; v1(17.22,35.7) 17.57,36.05 R75.2 C55.2 ; C36.2 v1(19.43,7.55)
  TOP w0.6: J15.5 19.7,45.67
  BOTTOM w0.25: 15.38,46.18 J15.9 ; J15.9 16.41,46.18 ; J15.9 15.38,45.15 ; J10.7 43.86,3.22 ; J10.7 43.86,1.86 ; J10.7 42.5,1.86 ; J10.7 42.5,3.22 ; 17.92,46.18 J15.5 18.95,46.18 ; J11.7 27.09,50.12 ; J11.7 25.74,50.12 ; J11.7 27.09,51.48 ; J11.7 25.74,51.48 ; 5.89,37.48 J17.4 ; J17.4 7.15,36.22 ; J17.4 7.15,37.48 ; J17.4 5.89,36.22 ; J12.6 66.84,26.08 ; J12.6 66.84,24.72 ; J12.6 65.49,24.72 ; J12.6 65.49,26.08 ; 39.96,1.86 J10.6 ; J10.6 39.96,3.22 ; J10.6 41.32,1.86 ; J10.6 41.32,3.22
  BOTTOM w0.5: 7.32,2.2 8.83,3.7 ; 8.83,3.7 10.33,2.2 ; 8.83,3.7 7.32,5.21 ; 8.83,3.7 10.33,5.21 ; J17.6 2.65,45.28 ; J17.6 2.65,42.96 ; J17.6 4.97,45.28 ; J17.6 4.97,42.96 ; J16.3 7.08,9.76 ; J16.3 4.07,9.76 ; J16.3 7.08,6.75 ; J16.3 4.07,6.75 ; 19.7,45.67 19.7,46.37 ; J17.5 4.97,33.24 ; J17.5 2.65,33.24 ; J17.5 4.97,30.92 ; J17.5 2.65,30.92
  BOTTOM w0.6: J15.5 19.7,45.67
  vias: v1(1.37,42.2) v1(2.42,34.4) v1(2.77,29) v1(2.97,0.9) v1(3.07,4.2) v1(3.27,16.1) v1(3.48,39.24) v1(4.77,50.2) v1(4.97,42.2) v1(5.02,11.1) v1(6.12,34.15) v1(6.67,14.35) v1(6.72,41.05) v1(6.72,25.4) v1(6.77,20.35) v1(7.07,45.3) v1(8.07,33.2) v1(8.27,51.9) v1(8.57,17.6) v1(8.57,6.5) v1(8.87,29.25) v1(9.47,12) v1(9.97,38.2) v1(10.17,31.4) v1(10.37,44.5) v1(11.07,1.4) v1(11.57,41.7) v1(12.07,24) v1(12.07,14.05) v1(12.77,31.75) v1(12.97,12) v1(13.07,20.65) v1(13.27,27.7) v1(13.77,44.8) v1(13.87,6.6) v1(14.57,20.5) v1(15.67,43.1) v1(15.97,22.3) v1(16.32,10.75) v1(16.77,40.4) v1(16.83,27.98) v1(16.82,15.85) v1(17.17,4.1) v1(17.34,49.13) v1(18.17,13.3) v1(18.22,11.25) v1(18.37,27.5) v1(18.72,35) v1(18.77,33.2) v1(19.02,26.2) v1(19.02,16) v1(18.97,12.7) v1(19.67,40.4) v1(19.67,16) v1(19.67,13.3) v1(19.87,16.6) v1(19.97,49) v1(20.27,1.3) v1(20.57,16.7) v1(20.67,42.2) v1(21.32,18.6) v1(21.62,32.15) v1(21.97,44.8) v1(22.07,28.4) v1(22.22,35.8) v1(22.27,5.8) v1(22.48,49.06) v1(22.47,16.95) v1(22.47,13.3) v1(22.82,37.95) v1(23.07,46.7) v1(23.67,30.25) v1(23.67,27.4) v1(23.67,7.65) v1(23.97,40.5) v1(24.07,18.55) v1(24.07,18) v1(24.12,33.95) v1(24.67,42.2) v1(24.62,18.55) v1(24.62,18) v1(24.67,13.1) v1(25.02,2.6) v1(25.17,18.55) v1(25.17,18) v1(25.27,38.55) v1(25.72,32.15) v1(25.72,18.55) v1(25.72,18) v1(26.32,18.55) v1(26.27,18) v1(26.37,10.9) v1(26.47,46.5) v1(27.07,35.85) v1(27.37,16.1) v1(27.52,28.55) v1(27.67,49.1) v1(27.92,37.85) v1(28.12,3.85) v1(28.42,12.2) v1(28.37,6.65) v1(28.82,23.7) v1(28.92,34.95) v1(28.92,19.2) v1(28.97,29.55) v1(28.97,27.25) v1(29.87,36.7) v1(30.37,46.9) v1(30.32,39.9) v1(30.47,31.5) v1(30.67,9.55) v1(30.72,14.55) v1(31.02,4.75) v1(31.22,34.8) v1(31.22,33.05) v1(32.22,18.85) v1(32.17,1.4) v1(32.97,11.6) v1(33.02,47.4) v1(33.42,31.2) v1(33.37,7.7) v1(33.47,49.35) v1(33.62,33.45) v1(34.12,41.17) v1(34.15,38.98) v1(34.62,35.8) v1(34.57,27.24) v1(34.92,23.65) v1(34.87,20.55) v1(35.37,4.2) v1(35.43,18.28) v1(35.59,33.4) v1(35.67,9.8) v1(35.77,22.5) v1(35.97,47.25) v1(36.72,12.45) v1(36.87,20.6) v1(37.37,18.75) v1(37.52,40.53) v1(37.77,33.65) v1(37.93,49.08) v1(37.97,14.2) v1(38.27,5.45) v1(38.8,22.75) v1(38.97,36.6) v1(39.19,33.44) v1(39.77,47.7) v1(39.72,11) v1(40.07,13.03) v1(40.27,7.3) v1(40.43,46.08) v1(40.52,15.7) v1(40.81,38.68) v1(40.93,41.28) v1(41.34,23.12) v1(41.91,29.94) v1(41.95,36.53) v1(41.95,33.7) v1(42.27,16.2) v1(42.57,13.6) v1(42.77,8.4) v1(43.05,21.03) v1(43.72,37.23) v1(43.83,50.18) v1(43.83,7.28) v1(43.97,47.35) v1(44.37,43.23) v1(44.33,16.88) v1(44.82,32.85) v1(44.82,12.45) v1(45.12,40.2) v1(45.23,20.98) v1(45.27,18.1) v1(45.77,15.55) v1(46.27,6.6) v1(46.67,47.15) v1(47.47,15.95) v1(47.72,38.1) v1(47.84,41.28) v1(48.27,43.7) v1(48.27,6.6) v1(48.37,13.45) v1(48.47,48.95) v1(48.57,33.75) v1(48.53,20.88) v1(48.63,2.98) v1(48.72,17.8) v1(49.97,19.1) v1(50.12,11.15) v1(50.32,33.8) v1(50.52,4.15) v1(50.57,14.1) v1(50.82,48.95) v1(50.82,41.25) v1(50.82,19.85) v1(51.17,20.9) v1(52.07,49.35) v1(52.52,14.3) v1(52.72,12.6) v1(52.92,33.05) v1(52.97,3.75) v1(53.12,20.6) v1(53.12,19.65) v1(53.12,18.8) v1(53.12,17.95) v1(53.14,22.38) v1(53.13,21.58) v1(53.27,30) v1(53.37,17.1) v1(53.32,6.4) v1(53.49,26.48) v1(53.52,7.95) v1(53.57,47.7) v1(54.02,49.7) v1(54.02,30) v1(54.42,11.3) v1(54.57,0.9) v1(54.77,30) v1(54.82,4.5) v1(55.23,15.88) v1(55.52,41.05) v1(55.47,29.65) v1(55.83,27.78) v1(55.83,26.68) v1(55.82,25.4) v1(55.82,24.15) v1(55.82,23.1) v1(55.83,21.98) v1(56.03,13.98) v1(56.23,15.88) v1(56.82,31.55) v1(56.87,5.3) v1(56.97,10.45) v1(57.07,35.1) v1(57.12,3.05) v1(57.27,45.95) v1(57.52,24.7) v1(57.43,15.88) v1(57.62,48.8) v1(57.93,12.48) v1(58.23,18.18) v1(58.53,23.08) v1(58.63,15.78) v1(58.72,27.05) v1(58.77,8.8) v1(58.93,21.58) v1(58.92,19.2) v1(58.92,18.4) v1(59.73,21.58) v1(59.73,14.58) v1(59.77,1.5) v1(59.97,41.8) v1(60.07,48.5) v1(60.32,3.95) v1(60.53,23.18) v1(60.53,21.58) v1(60.67,35.7) v1(60.63,14.58) v1(60.63,13.58) v1(60.63,12.58) v1(60.63,11.58) v1(60.63,10.58) v1(60.63,9.58) v1(60.63,8.58) v1(60.67,7.6) v1(60.67,6.6) v1(60.97,29.2) v1(61.07,32.85) v1(61.42,26.15) v1(61.53,23.78) v1(62.53,23.78) v1(62.67,32.55) v1(63.02,48.85) v1(63.53,23.78) v1(63.83,36.58) v1(64.33,40.28) v1(64.37,26.9) v1(64.53,23.78) v1(65.03,44.38) v1(65.53,23.78) v1(66.53,23.78) v1(67.33,32.48) v1(67.47,26.7) v1(67.53,23.78)
VDD_PLAT_1P8: length 4
  TOP w0.14: U12.M2 37.45,24.95 36.97,24.95 36.87,24.85
  TOP w0.4: C28.1 34.11,24.7 36.29,24.7 36.44,24.85 36.87,24.85
VDD_PLAT_3P3: length 109.5
  TOP w0.116: U12.H22 47.03,27.23 47.37,27.23 U12.H24
  TOP w0.14: U12.K2 37.45,26.66 37.06,26.66 36.99,26.73
  TOP w0.25: U12.E21 46.29,29.21 v1(45.16,29.21) ; U12.H24 47.85,27.52 48.03,27.34 48.61,27.34 48.71,27.24 ; 36.8,26.92 36.99,26.73 ; 36.8,26.92 36.8,27.15 36.72,27.23 36.72,27 36.8,26.92 ; R10.1 58.91,34.2 v1(56.07,34.2)
  TOP w0.3: 49.04,26.9 48.71,27.24
  TOP w0.4: v1(36.3,27.65) 36.72,27.23 ; 49.04,26.9 49.57,26.9 50.02,26.45 v1(50.91,26.45) 50.91,26.4 51.4,25.91 R35.2 51.57,24.8 C21.1 51.43,24.66 C22.1 ; R30.1 51.56,31.75 51.67,31.75 v1(51.77,31.85)
  TOP w0.5: v1(28.37,28.8) 28.37,28.04 R58.1
  TOP w0.55: 24.07,37.75 U16.5 25.03,37.14
  TOP w0.6: 25.03,37.14 R15.1 R16.1 25.03,34.04 v1(25.32,33.75) ; 24.07,37.75 23.17,38.65 23.17,44.7 22.2,45.67 J15.1 ; R34.1 47.32,13.73 v1(47.32,14.5) ; v1(31.47,27.95) 31.47,17.9 32.67,16.7 34.63,16.7 34.87,16.94 C44.1 35.91,17.17 U201.8 U201.7 v1(38.84,16.06)
  BOTTOM w0.25: TPB21.1 50.87,33.2 51.27,33.6 55.47,33.6 v1(56.07,34.2)
  BOTTOM w0.4: TPB21.1 51.42,31.85 v1(51.77,31.85)
  BOTTOM w0.5: 50.82,32.35 50.82,31.09 50.05,30.32 50.05,28.45 50.91,27.59 v1(50.91,26.45) ; 50.82,32.35 TPB21.1 ; 50.82,32.35 49.32,32.35 49.22,32.25 48.27,32.25 47.99,32.53 47.15,32.53 46.77,32.15 46.77,31.8 45.57,30.6 45.57,29.95 45.16,29.54 v1(45.16,29.21) 45.16,28.7 44.52,28.06 44.52,27.63 44.19,27.3 42.74,27.3 41.87,26.42 40.24,26.42 39.02,27.65 v1(36.3,27.65)
  BOTTOM w0.6: v1(25.32,33.75) 28.27,30.8 28.27,28.9 v1(28.37,28.8) 29.22,27.95 v1(31.47,27.95) 35.99,27.95 v1(36.3,27.65) ; v1(47.32,14.5) 39.82,14.5 38.84,15.48 v1(38.84,16.06)
AD0: length 7.8
  TOP w0.15: J14.1 49.92,3.42 49.92,4.95 48.81,6.06 U15.11
AD1: length 8.6
  TOP w0.15: J14.2 53.34,2.64 49.46,6.52 U15.12
AD2: length 10.3
  TOP w0.15: U15.13 50.11,8.3 50.07,8.27 50.07,6.9 52.72,4.25 54.17,4.25 J14.3
AD3: length 12
  TOP w0.15: U15.14 50.76,8.3 50.67,8.22 50.67,7.3 52.87,5.1 55.86,5.1 J14.4
AD4_SDA: length 108.8
  TOP w0.15: J14.5 57.6,5.9 53.11,5.9 51.42,7.59 v1(51.42,7.6) 51.41,7.61 U15.15 ; v1(17.37,11.15) 17.37,11.85 16.57,12.65 11.82,12.65 7.27,17.2 7.27,33.8 5.07,36 5.07,40.4 7.67,43 10.77,43 14.62,46.85 19.57,46.85 21.34,48.62 J11.9
  BOTTOM w0.15: v1(17.37,11.15) 17.62,11.15 19.37,9.4 28.32,9.4 29.22,10.3 37.37,10.3 39.77,7.9 44.57,7.9 44.87,7.6 v1(51.42,7.6)
AD5_SCL: length 116.1
  TOP w0.15: 4.37,40.73 7.37,43.73 10.54,43.73 14.36,47.54 17.71,47.54 18.8,48.63 J11.10 ; 4.37,40.73 4.35,40.7 4.35,35.17 4.37,35.15 ; 4.37,40.73 4.37,35.15 ; 4.37,35.15 6.22,33.3 6.22,16.85 11.67,11.4 16.32,11.4 v1(16.47,11.55) ; J14.6 62.57,2.54 58.21,6.9 53.32,6.9 52.37,7.85 v1(52.37,8.25) 52.06,8.56 U15.16
  BOTTOM w0.15: v1(52.37,8.25) 51.97,8.25 51.87,8.35 45.42,8.35 44.87,8.9 39.87,8.9 37.77,11 28.82,11 28.02,10.2 20.02,10.2 18.27,11.95 16.87,11.95 v1(16.47,11.55)
AD09/SS1_3V_AD5: length 23.3
  TOP w0.116: U12.K21 45.97,26.38 45.95,26.36 45.87,26.36 ; 48.07,24.5 48.04,24.5 47.91,24.63 47.68,24.63 U12.N24
  TOP w0.15: 48.07,24.5 48.24,24.5 48.56,24.19 v1(49.27,24.19) 49.34,24.12 50.37,24.12 50.65,23.84 50.65,20.72 51.67,19.7 51.67,16.5 52.06,16.11 U15.5 ; 45.87,26.36 44.31,26.36 44.11,26.56 v1(44.11,26.58)
  BOTTOM w0.15: v1(44.11,26.58) 44.68,27.15 47.13,27.15 47.55,27.58 48.69,27.58 49.34,26.92 49.34,24.39 49.27,24.32 v1(49.27,24.19)
AD10/SS2_3V_AD0: length 18.6
  TOP w0.116: 39.07,26.9 39.07,26.94 38.78,27.23 38.02,27.23 U12.J2
  TOP w0.15: v1(48.27,17.2) 48.27,16.65 48.81,16.11 U15.10 ; v1(42.74,20.42) 42.57,20.6 42.57,21.98 42.65,22.05 42.65,23.33 39.07,26.9
  BOTTOM w0.15: v1(42.74,20.42) 42.8,20.38 43.34,20.38 44.12,19.6 45.97,19.6 48.27,17.3 v1(48.27,17.2)
AD11/SS3_3V_AD1: length 18.4
  TOP w0.116: U12.H21 46.23,27.45 45.64,27.45 45.49,27.6 45.3,27.6 v1(45.15,27.74)
  TOP w0.15: U15.9 49.46,16.11 49.21,16.36 49.21,21.62 49.57,21.97 49.57,23.23 v1(49.62,23.28)
  BOTTOM w0.15: v1(49.62,23.28) 49.62,23.72 49.73,23.83 49.73,24.38 49.62,24.49 49.62,27.03 48.8,27.86 48.57,27.86 48.57,27.85 47.44,27.85 47.44,27.85 47.42,27.85 46.99,27.42 45.47,27.42 v1(45.15,27.74)
AD12/SS4_3V_AD2: length 20.3
  TOP w0.116: 39.07,27.32 39.07,27.6 38.87,27.8 38.02,27.8 U12.H2
  TOP w0.15: v1(43.05,21.67) 42.95,21.78 42.95,23.45 39.07,27.32 ; v1(50.02,18) 49.87,17.85 49.87,16.4 50.11,16.16 U15.8
  BOTTOM w0.15: v1(43.05,21.67) 43.27,21.67 44.55,20.4 46.43,20.4 48.38,18.45 49.57,18.45 v1(50.02,18)
AD13/SS5_3V_AD3: length 22.3
  TOP w0.116: U12.L2 38.02,25.52 38.8,25.52 38.9,25.42 39.05,25.42 39.07,25.4
  TOP w0.15: U15.7 50.67,15.52 50.67,16.2 50.37,16.5 v1(50.37,17) ; 39.07,25.4 40.02,24.45 40.02,19.35 v1(40.07,19.3)
  BOTTOM w0.15: v1(40.07,19.3) 40.27,19.5 42.97,19.5 43.62,18.85 45.47,18.85 48.39,15.92 49.69,15.92 50.37,16.6 v1(50.37,17)
AD14/SS6_3V_AD4: length 23.1
  TOP w0.116: U12.N23 47.48,24.38 47.81,24.38 47.97,24.23 48.07,24.23 ; U12.C24 47.84,30.37 48.03,30.56 48.08,30.56 48.16,30.64
  TOP w0.15: U15.6 51.41,16.06 50.97,16.5 50.97,19 49.97,20 49.97,21.53 50.09,21.65 50.09,23.55 v1(50.2,23.65) 50.11,23.73 49.08,23.73 48.93,23.88 48.47,23.88 48.12,24.23 48.07,24.23 ; 48.16,30.64 48.4,30.88 48.4,31.37 48.32,31.45 v1(48.32,31.6)
  BOTTOM w0.15: v1(50.2,23.65) 50.2,23.8 50.01,23.99 50.01,24.49 49.9,24.6 49.9,27.15 48.82,28.23 48.82,28.45 47.87,29.4 47.87,30.8 48.32,31.25 v1(48.32,31.6)
ATPCTS/IO9_3V_IO14: length 22.9
  TOP w0.116: U12.J22 46.46,27.23 46.02,27.23 45.98,27.19 45.83,27.19
  TOP w0.15: v1(34.02,31.75) 34.22,31.95 34.22,34.8 34.12,34.9 34.12,36 34.4,36.28 U14.4 ; v1(43.89,27.94) 44.08,27.75 44.45,27.75 44.92,27.28 45.45,27.28 45.54,27.19 45.83,27.19
  BOTTOM w0.15: v1(34.02,31.75) 34.22,31.95 34.97,31.95 35.37,31.55 35.77,31.55 36.67,32.45 38.65,32.45 38.77,32.33 39.24,32.33 39.58,31.98 39.58,31.68 40.24,31.02 40.24,30.54 40.62,30.16 40.62,29.2 41.2,28.62 41.99,28.62 42.82,27.8 43.74,27.8 v1(43.89,27.94)
ATPMISO/IO1_3V_IO12: length 27.3
  TOP w0.116: 38.8,28.37 38.48,28.37 U12.G3 ; U12.B22 46.46,31.22 46.15,31.22 45.96,31.41 45.96,31.95
  TOP w0.15: v1(41.47,37.3) 41.47,33.15 v1(41.77,32.85) 41.74,32.82 41.74,31.23 41.45,30.94 41.45,29.72 41.84,29.33 41.84,28.9 40.92,27.98 39.2,27.98 38.8,28.37 ; 45.96,31.95 45.96,31.96 45.8,32.12 v1(45.8,32.25) ; U14.6 v1(35.7,36.65)
  BOTTOM w0.15: v1(41.77,32.85) 41.72,32.8 41.72,32.57 42.21,32.08 45.65,32.08 45.8,32.23 v1(45.8,32.25) ; v1(41.47,37.3) 41.32,37.45 39.77,37.45 39.43,37.79 36.83,37.79 36.11,37.07 35.91,37.07 35.7,36.86 v1(35.7,36.65)
ATPMOSI/IO3_3V_IO11: length 24.4
  TOP w0.116: U12.E22 46.46,28.94 46.14,28.94 46.08,28.89 45.87,28.89
  TOP w0.15: v1(44.52,29) 44.77,28.75 45.34,28.75 45.35,28.76 45.48,28.89 45.87,28.89 ; U14.7 v1(36.34,36.65) ; v1(40.92,36.9) 40.92,36.25 41.17,36 41.17,32.79 41.46,32.5 41.46,31.34 41.18,31.06 41.18,29.29 v1(41.37,29.1) 41.37,28.95 40.67,28.25 39.32,28.25 38.91,28.66 U12.F4
  BOTTOM w0.15: v1(41.37,29.1) 41.52,28.95 42.12,28.95 42.97,28.1 43.37,28.1 43.67,28.4 44.07,28.4 44.52,28.85 v1(44.52,29) ; v1(36.34,36.65) 36.34,36.86 36.98,37.49 39.28,37.49 39.62,37.15 40.67,37.15 v1(40.92,36.9)
ATPSCK/IO2_3V_IO13: length 33.8
  TOP w0.15: U12.E4 39.16,29.23 39.56,28.83 40.3,28.83 40.62,29.15 40.62,31.3 40.5,31.42 40.5,32.15 v1(40.62,32.27) 40.59,32.3 40.59,35.68 39.84,36.43 39.84,37.97 v1(40.12,38.25) ; U16.2 28.11,38.7 R65.1 v1(28.85,38.18) ; U14.5 v1(35.05,38.72) ; U12.C21 46.27,30.4 45.82,30.4 v1(44.92,31.3)
  BOTTOM w0.15: v1(44.92,31.3) 44.82,31.3 44.65,31.48 41.92,31.48 41.21,32.19 40.7,32.19 v1(40.62,32.27) ; v1(40.12,38.25) 39.98,38.39 35.37,38.39 v1(35.05,38.72) 34.23,37.9 29.13,37.9 v1(28.85,38.18)
ATPSS/IO0_3V_IO10: length 22.7
  TOP w0.116: U12.F3 38.48,28.94 39.05,28.94 39.07,28.92 ; U12.D22 46.48,30.07 46.11,30.07 46.06,30.12 45.87,30.12
  TOP w0.15: v1(44.51,30.79) 44.57,30.73 45.1,30.73 45.7,30.12 45.87,30.12 ; v1(40.31,36.65) 40.31,36.41 40.87,35.85 40.87,32.67 41.11,32.43 41.11,31.81 v1(40.99,31.7) 40.99,31.32 40.9,31.23 40.9,29 40.42,28.53 39.47,28.53 39.07,28.92 ; U14.8 v1(36.99,36.65)
  BOTTOM w0.15: v1(40.99,31.7) 41.16,31.53 41.42,31.53 41.77,31.17 44.09,31.17 44.48,30.79 v1(44.51,30.79) ; v1(36.99,36.65) 36.99,36.95 37.23,37.19 39.13,37.19 39.47,36.85 40.11,36.85 v1(40.31,36.65)
BT_ANT_50: length 15.4
  TOP w1.016: R18.1 C38.2 55.11,17.06 54.33,17.84 54.33,22.31 54.63,22.61 C46.2 RLC12.2
BT_AOUT_50: length 4.8
  TOP w0.35: 49.43,28.76 49.39,28.73 48.72,28.73 48.57,28.88 48.05,28.88 47.82,28.66 U12.F24
  TOP w0.6: C47.2 51.11,28.8
  TOP w0.65: 49.43,28.76 C47.2
  TOP w1.016: 51.11,28.8 RLC12.1
CURIE_VBUS: length 16.5
  TOP w0.65: 24.02,28.8 R59.2
  TOP w0.7: R12.2 11.88,30.79 12.67,30 v1(12.67,28.9)
  TOP w0.8: 24.02,28.8 23.66,28.8 23.16,29.3 v1(21.77,29.3)
  BOTTOM w0.8: v1(12.67,28.9) 18.77,28.9 19.17,29.3 v1(21.77,29.3)
DBG_AP_JTAG_TCK: length 53.3
  TOP w0.116: U12.L23 47.48,25.52 47.79,25.52 47.95,25.37 47.95,25.12 48.07,25
  TOP w0.15: v1(48.97,29.3) 48.92,29.35 48.92,29.45 48.84,29.53 48.84,30.12 49.67,30.95 49.67,31.7 49.27,32.1 49.27,34.27 46.72,36.82 46.72,38.57 45.82,39.47 45.82,43.05 v1(45.47,43.4) ; 48.07,25 48.3,24.78 48.45,24.78 48.58,24.64 50.41,24.64 v1(50.45,24.61)
  BOTTOM w0.15: 19.7,44.4 20.5,43.6 30,43.6 30.5,44.1 34.37,44.1 35.02,43.45 36.2,43.45 36.45,43.7 45.17,43.7 v1(45.47,43.4) 45.47,43.35 TPB13.1 ; v1(50.45,24.61) 50.17,24.88 50.17,27.27 49.17,28.28 49.17,29.2 49.07,29.3 v1(48.97,29.3)
DBG_AP_JTAG_TDI: length 50.1
  TOP w0.15: v1(42.42,42.65) 42.2,42.42 42.2,41.73 42.7,41.23 42.7,33.89 42.91,33.68 42.91,31.99 42.65,31.73 42.65,28.53 42.59,28.48 42.59,26.88 44.59,24.88 45.64,24.88 45.96,25.2 46.27,25.2 U12.M21
  BOTTOM w0.15: J15.8 17.96,43.59 17.97,43.6 18.72,43.6 19.07,43.25 19.82,43.25 20.07,43 30.24,43 30.74,43.5 34.09,43.5 34.74,42.85 36.44,42.85 36.69,43.1 41.52,43.1 41.97,42.65 v1(42.42,42.65) 42.67,42.65 43.12,42.2 43.88,42.2 44.03,42.35 TPB15.1
DBG_AP_JTAG_TDO: length 49.3
  TOP w0.116: 45.87,24.72 46.1,24.95 46.91,24.95 U12.M23
  TOP w0.15: v1(42.07,43.24) 41.9,43.07 41.9,41.58 42.42,41.05 42.42,33.76 42.62,33.56 42.62,32.13 42.37,31.88 42.37,28.65 42.31,28.59 42.31,26.75 44.49,24.58 45.73,24.58 45.87,24.72
  BOTTOM w0.15: TPB14.1 43.18,43.24 v1(42.07,43.24) 41.91,43.4 36.57,43.4 36.32,43.15 34.87,43.15 34.22,43.8 30.62,43.8 30.12,43.3 20.27,43.3 19.97,43.6 19.23,43.6 J15.6
DBG_AP_JTAG_TMS: length 51.6
  TOP w0.116: U12.L24 47.7,25.75 47.9,25.75 48.17,25.48 48.17,25.3
  TOP w0.15: v1(50.64,25.36) 50.61,25.36 50.44,25.19 50.32,25.19 50.05,24.92 48.69,24.92 48.56,25.05 48.42,25.05 48.17,25.3 ; v1(46.09,43.6) 46.09,39.59 47,38.69 47,36.94 49.55,34.39 49.55,32.22 49.97,31.79 49.97,30.84 49.32,30.19 49.32,29.85 v1(49.37,29.8)
  BOTTOM w0.15: J15.2 21.47,43.9 29.85,43.9 30.35,44.4 34.49,44.4 35.14,43.75 36.07,43.75 36.32,44 45.7,44 v1(46.09,43.6) 47.17,43.6 TPB12.1 ; v1(50.64,25.36) 50.45,25.55 50.45,27.39 49.47,28.38 49.47,29.7 v1(49.37,29.8)
DBG_AP_JTAG_TRST_N: length 49.8
  TOP w0.116: 45.87,26.08 46.91,26.08 U12.K23
  TOP w0.15: v1(42.67,41.95) 42.82,41.81 42.82,41.55 42.97,41.4 42.97,34.05 43.2,33.82 43.2,31.87 42.92,31.59 42.92,28.42 42.87,28.36 42.87,27.03 43.87,26.03 44.49,26.03 44.55,26.08 45.87,26.08
  BOTTOM w0.15: J15.10 16.69,43.6 17.42,43.6 17.77,43.25 18.57,43.25 18.92,42.9 19.67,42.9 19.87,42.7 30.37,42.7 30.87,43.2 33.97,43.2 34.62,42.55 36.57,42.55 36.82,42.8 41.37,42.8 42.22,41.95 v1(42.67,41.95) 42.93,41.7 43.42,41.7 TPB16.1
DC_IN_5V_20V: length 73
  TOP w0.6: R83.1 22.01,37.66 v1(22.17,37.5) R81.1 ; v1(31.62,8.5) 31.62,15.8 30.12,17.3 v1(30.12,30.75)
  TOP w0.65: 22.17,8.29 L13.1
  TOP w0.7: C50.1 v1(22.17,6.7) ; C36.1 v1(21.47,6.7)
  TOP w0.75: v1(22.17,6.7) 22.17,8.29
  TOP w0.8: D17.K 21.47,8.8 v1(21.47,6.7) v1(22.17,6.7) ; J10.8 45.47,2.79 45.47,3.6 44.22,4.85 v1(44.22,6.35) v1(43.57,6.35)
  BOTTOM w0.6: v1(22.17,37.5) 22.47,37.2 23.67,37.2 v1(30.12,30.75)
  BOTTOM w0.8: v1(44.22,6.35) v1(43.57,6.35) 38.92,6.35 36.77,8.5 v1(31.62,8.5) 29.92,8.5 28.87,7.45 24.62,7.45 23.87,6.7 v1(22.17,6.7) v1(21.47,6.7)
DC_IN_5V_20V_FIL: length 2.5
  TOP w0.65: D18.A 26.57,9.2 L13.2
DC_IN_JACK: length 8.6
  TOP w1.7: D17.A 15.93,8.26 11.74,8.26
  BOTTOM w1: 11.74,8.26 11.67,8.32 TPB20.1
I2S_TSCK/IO18_3V_IO2: length 24.4
  TOP w0.116: U12.C2 37.45,30.65 37.17,30.65
  TOP w0.15: U11.8 v1(53.7,36.65) ; v1(36.77,34.5) 36.37,34.1 36.37,31.1 36.82,30.65 37.17,30.65
  BOTTOM w0.15: v1(36.77,34.5) 36.97,34.3 42.77,34.3 43.52,35.05 44.27,35.05 44.39,34.93 52.1,34.93 53.7,36.52 v1(53.7,36.65)
I2S_TWS/IO19_3V_IO4: length 23.7
  TOP w0.15: U12.C1 36.7,30.37 36.06,31.01 36.06,34.54 36.66,35.14 v1(36.67,35.14) ; 52.39,37.65 v1(52.39,36.65)
  BOTTOM w0.15: v1(52.39,36.65) 52.39,36.52 51.4,35.53 44.69,35.53 44.57,35.65 43.22,35.65 42.47,34.9 37.97,34.9 37.57,35.3 36.82,35.3 36.67,35.15 v1(36.67,35.14)
I2S_TXD/IO20_3V_IO7: length 24
  TOP w0.15: U11.3 v1(50.45,36.65) ; v1(35.57,35.6) 35.42,35.45 35.42,34.8 35.12,34.5 35.12,31.85 35.47,31.5 35.47,30.8 36.48,29.8 U12.D1
  BOTTOM w0.15: v1(35.57,35.6) 35.87,35.9 37.57,35.9 37.77,36.1 38.52,36.1 38.82,35.8 42.02,35.8 42.77,36.55 45.02,36.55 45.14,36.43 50.23,36.43 v1(50.45,36.65)
IO0/RXD: length 12.6
  TOP w0.15: J13.1 59.5,46.8 56.37,46.8 54.99,45.42 U11.11
IO1/TXD: length 11.2
  TOP w0.15: U11.12 54.34,46.28 56.07,48 58.16,48 J13.2
IO2: length 9.8
  TOP w0.15: U11.13 53.7,47.12 55.67,49.1 56.72,49.1 J13.3
IO3/PWM0: length 8.4
  TOP w0.15: J13.4 53.05,47.97 U11.14
IO4: length 7.6
  TOP w0.15: J13.5 53.34,49.69 52.39,48.74 52.39,43.55
IO5/PWM1: length 7.6
  TOP w0.15: U11.16 51.74,48.73 50.8,49.67 J13.6
IO6/PWM2: length 8.4
  TOP w0.15: J13.7 51.09,47.97 U11.17
IO7: length 9.9
  TOP w0.15: J13.8 48.22,48.3 49.37,48.3 50.45,47.23 U11.18
IO8: length 8.6
  TOP w0.15: J11.1 41.66,48.59 38.3,45.23 U14.11
IO9/PWM3: length 7.9
  TOP w0.15: J11.2 39.12,47.4 37.65,45.92 37.65,43.55
IO10/SS: length 7.4
  TOP w0.15: J11.3 36.58,47.44 36.99,47.03 U14.13
IO11/MOSI: length 48
  TOP w0.15: J11.4 34.04,48.53 36.33,46.24 36.33,45.45 v1(36.43,45.36) 36.34,45.27 U14.14
  BOTTOM w0.15: v1(36.43,45.36) 36.58,45.2 53.67,45.2 63.07,35.8 63.07,33.7 64.95,31.83 64.95,29.16 J12.4
IO12/MISO: length 45.1
  TOP w0.15: U14.15 35.7,44.53 v1(35.72,44.55) 35.72,45.45 31.5,49.67 J11.5
  BOTTOM w0.15: v1(35.72,44.55) 35.77,44.6 53.42,44.6 62.47,35.55 62.47,33.45 63.63,32.29 J12.1
IO13/SCK: length 49.2
  TOP w0.15: J11.6 33.46,46.3 33.87,46.3 35.05,45.12 v1(35.05,44.55) U14.16
  BOTTOM w0.15: v1(35.05,44.55) 35.55,44.05 35.95,44.05 36.2,44.3 53.3,44.3 62.17,35.43 62.17,29.4 J12.3
IO14_NEW: length 46.8
  TOP w0.15: v1(32.73,41.5) 32.9,41.67 33.36,41.67 34.4,42.71 U14.17 ; v1(32.07,5) 32.47,5.4 32.47,16.15 30.96,17.66 30.96,30.69 32.07,31.8 32.07,36.06 31.37,36.76 31.37,38.64 v1(31.53,38.8)
  BOTTOM w0.15: v1(31.53,38.8) 31.53,39.36 32.37,40.2 32.37,40.88 32.56,41.07 32.56,41.32 v1(32.73,41.5) ; J10.1 29,3.6 30.67,3.6 v1(32.07,5)
M_RESET: length 41.1
  TOP w0.116: U12.D23 46.91,29.51 46.01,29.51 45.97,29.55
  TOP w0.15: v1(10.37,29.01) 10.36,29 R13.2 ; v1(44.52,29.67) 44.62,29.78 45.25,29.78 45.48,29.55 45.97,29.55 ; v1(21.22,30.8) 25.27,30.8 26.67,32.2 30.17,32.2 v1(30.67,32.7)
  BOTTOM w0.15: v1(21.22,30.8) 20.37,29.95 18.87,29.95 18.47,29.55 10.91,29.55 v1(10.37,29.01) ; v1(30.67,32.7) 30.84,32.53 36.3,32.53 36.52,32.75 38.77,32.75 38.9,32.62 39.37,32.62 39.87,32.12 39.87,31.78 40.72,30.93 41.18,30.93 41.54,30.58 43.59,30.58 44.32,29.85 44.37,29.85 44.47,29.75 44.47,29.73 v1(44.52,29.67)
MISO1/IO9_3V_IO8: length 14.6
  TOP w0.116: 39.07,29.51 38.48,29.51 U12.E3 ; U12.B2 38.02,30.65 38.91,30.65
  TOP w0.15: U14.10 38.3,36.58 40.3,34.57 40.3,32.64 40.14,32.48 40.14,31.31 ; 40.14,31.31 39.57,31.31 38.91,30.65 ; 40.14,31.31 40.34,31.11 40.34,29.31 40.13,29.1 39.69,29.1 39.29,29.51 39.07,29.51
NOR_SWD_SCL: length 3.1
  TOP w0.116: U12.D24 47.65,29.83 48.11,30.29
  TOP w0.15: v1(48.92,31.35) 48.92,31 48.21,30.29 48.11,30.29
  BOTTOM w0.15: TPB11.1 48.97,31.4 v1(48.92,31.35)
NOR_SWD_SDA: length 1.8
  TOP w0.116: 48.07,29.3 47.97,29.3 47.89,29.23 U12.E24
  TOP w0.15: v1(48.37,29.55) 48.12,29.3 48.07,29.3
  BOTTOM w0.15: TPB10.1 48.67,29.85 v1(48.37,29.55)
PV_BATT: length 5.1
  TOP w0.25: U12.M1 37.29,25.23 37.2,25.33 36.15,25.33 36.09,25.28
  TOP w0.4: 36.09,25.28 35.4,25.28 34.77,25.9 34.21,25.9 C24.1 33.92,26.19 33.92,27.29 C23.1
PWM0/SS10_3V_IO3: length 30.2
  TOP w0.15: U11.7 v1(53.05,36.65) ; U12.B1 36.94,30.94 36.72,31.15 36.72,31.85 v1(36.84,31.98) 36.72,32.1 36.72,33.75 37.37,34.4 37.37,34.84 v1(37.36,34.84) ; U12.H1 37.01,27.8 36.8,27.8 35.3,29.3 34.85,29.3 34.39,29.76 v1(34.39,30.62)
  BOTTOM w0.15: v1(37.36,34.84) 37.37,34.84 37.53,34.84 37.77,34.6 42.62,34.6 43.37,35.35 44.42,35.35 44.54,35.23 51.75,35.23 53.05,36.53 v1(53.05,36.65) ; v1(36.84,31.98) 36.59,31.73 36.4,31.73 35.29,30.62 v1(34.39,30.62)
